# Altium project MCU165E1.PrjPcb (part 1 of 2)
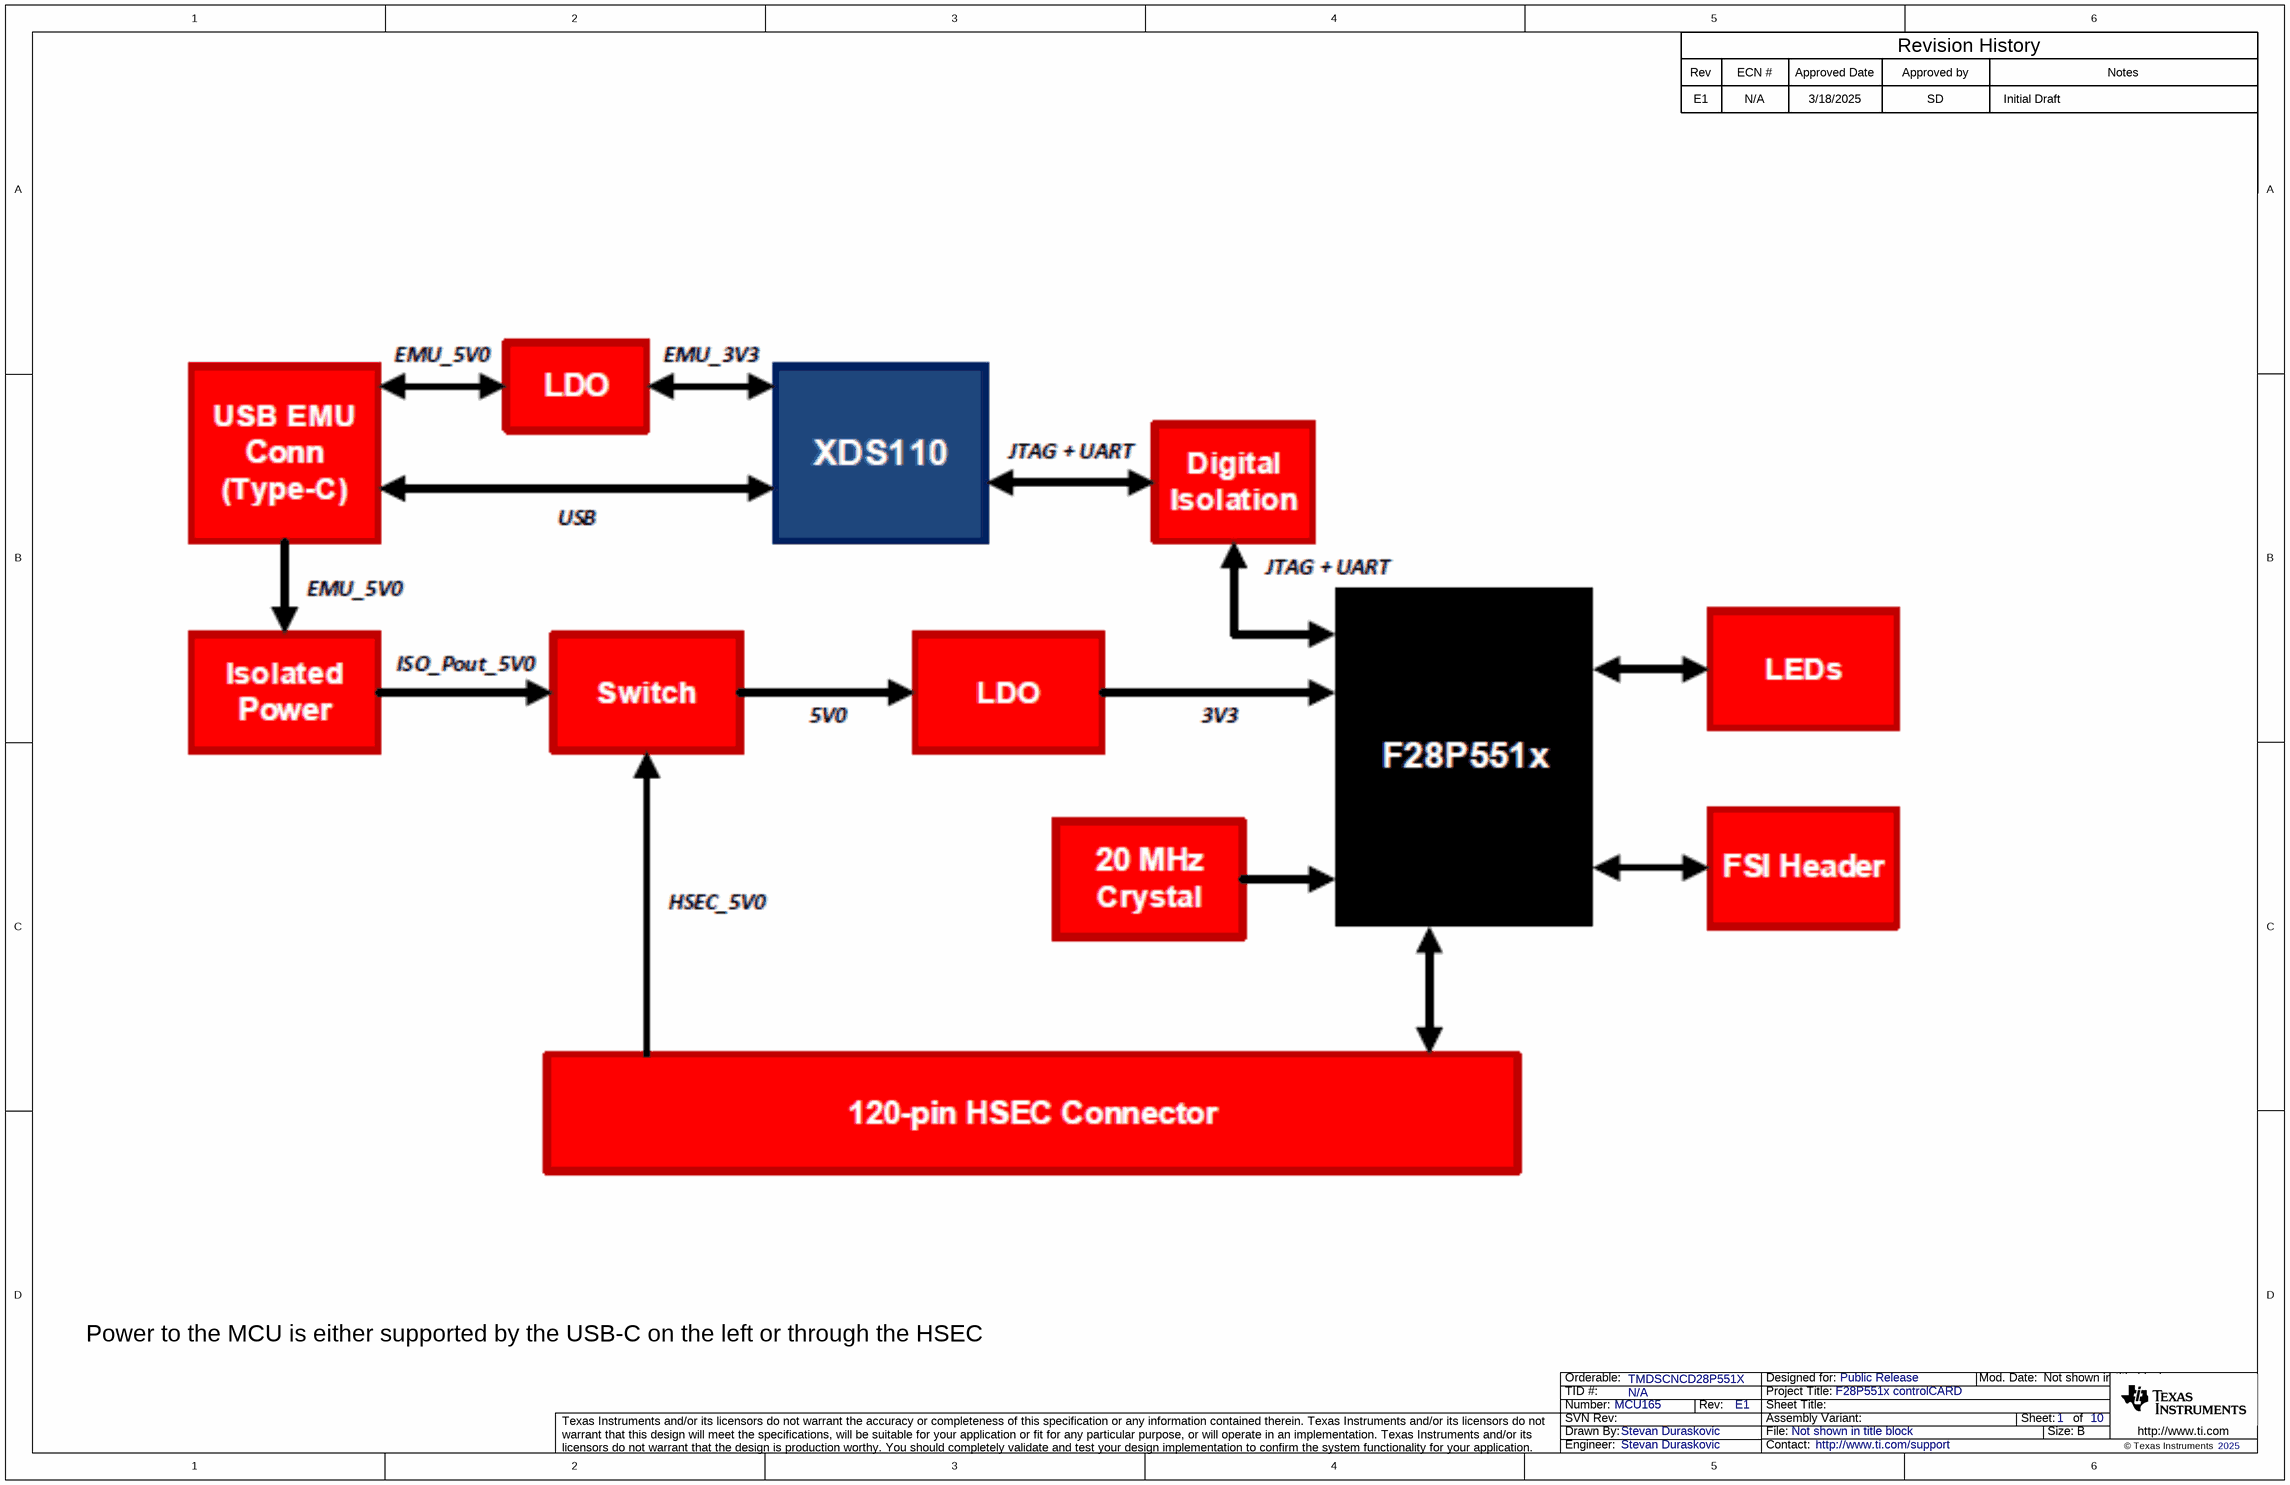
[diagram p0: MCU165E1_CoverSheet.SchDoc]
CopyrightYear: 2025; DrawnBy: Stevan Duraskovic; EVM_Orderable: TMDSCNCD28P551X; PCB_Layout: Stevan Duraskovic; PCB_Rev: E1; PRJ_Customer: Public Release; PRJ_Engineer: Stevan Duraskovic; PRJ_Number: MCU165; PRJ_Title: F28P551x controlCARD; SCH_Rev: E1; TechSupport: http://www.ti.com/support; TID: N/A
9 sheets, 227 parts. Net scope: global (net labels, ports and power ports of the same name join across sheets).
Board file: MCU165E1_PCB.PcbDoc
Sheets:
  MCU165E1_CoverSheet.SchDoc
  MCU165E1_GPIO.SchDoc
  MCU165E1_Support.SchDoc
  MCU165E1_Power.SchDoc
  MCU165E1_ADC.SchDoc
  MCU165E1_XDS110_USB_Power.SchDoc
  MCU165E1_XDS110_MCU.SchDoc
  MCU165E1_Emulator_Interface.SchDoc
  MCU165E1_Hardware.SchDoc

## Sheet MCU165E1_CoverSheet.SchDoc
size 431 x 279 mm; Date: Not shown in title block; ApprovedBy: Not shown in title block; CheckedBy: Not shown in title block; Author: Not shown in title block; CompanyName: Not shown in title block; Engineer: Not shown in title block; Organization: Not shown in title block; Address1: Not shown in title block; Address2: Not shown in title block; Address3: Not shown in title block; Address4: Not shown in title block; DocumentNumber: 1; Revision: Use project parameter SCH_Rev; SheetNumber: 1; SheetTotal: 10; PageSetup: Record=PageOptions¦CenterHorizontal=True¦CenterVertical=True¦PrintScale=1.00¦XCorrection=1.00¦YCorrection=1.00¦PrintKind=0¦BorderSize=5000000¦LeftOffset=0¦BottomOffset=0¦Orientation=2¦PaperLength=1000¦PaperWidth=1000¦Scale=100¦PaperSource=15¦PrintQuality=600¦MediaType=1¦DitherType=10¦PaperKind=Letter¦PrintScaleMode=1

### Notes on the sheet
- Rev
- E1
- ECN #
- N/A
- Approved Date
- 3/18/2025
- Approved by
- SD
- Revision History
- Initial Draft
- Notes
- Power to the MCU is either supported by the USB-C on the left or through the HSEC 180 pin.

## Sheet MCU165E1_GPIO.SchDoc
size 431 x 279 mm; Date: Not shown in title block; ApprovedBy: Not shown in title block; CheckedBy: Not shown in title block; Author: Not shown in title block; CompanyName: Not shown in title block; Engineer: Not shown in title block; Organization: Not shown in title block; Address1: Not shown in title block; Address2: Not shown in title block; Address3: Not shown in title block; Address4: Not shown in title block; DocumentNumber: 2; Revision: Use project parameter SCH_Rev; SheetNumber: 2; SheetTotal: 10; PageSetup: Record=PageOptions¦CenterHorizontal=True¦CenterVertical=True¦PrintScale=1.00¦XCorrection=1.00¦YCorrection=1.00¦PrintKind=0¦BorderSize=5000000¦LeftOffset=0¦BottomOffset=0¦Orientation=2¦PaperLength=1000¦PaperWidth=1000¦Scale=100¦PaperSource=15¦PrintQuality=600¦MediaType=1¦DitherType=10¦PaperKind=Letter¦PrintScaleMode=1
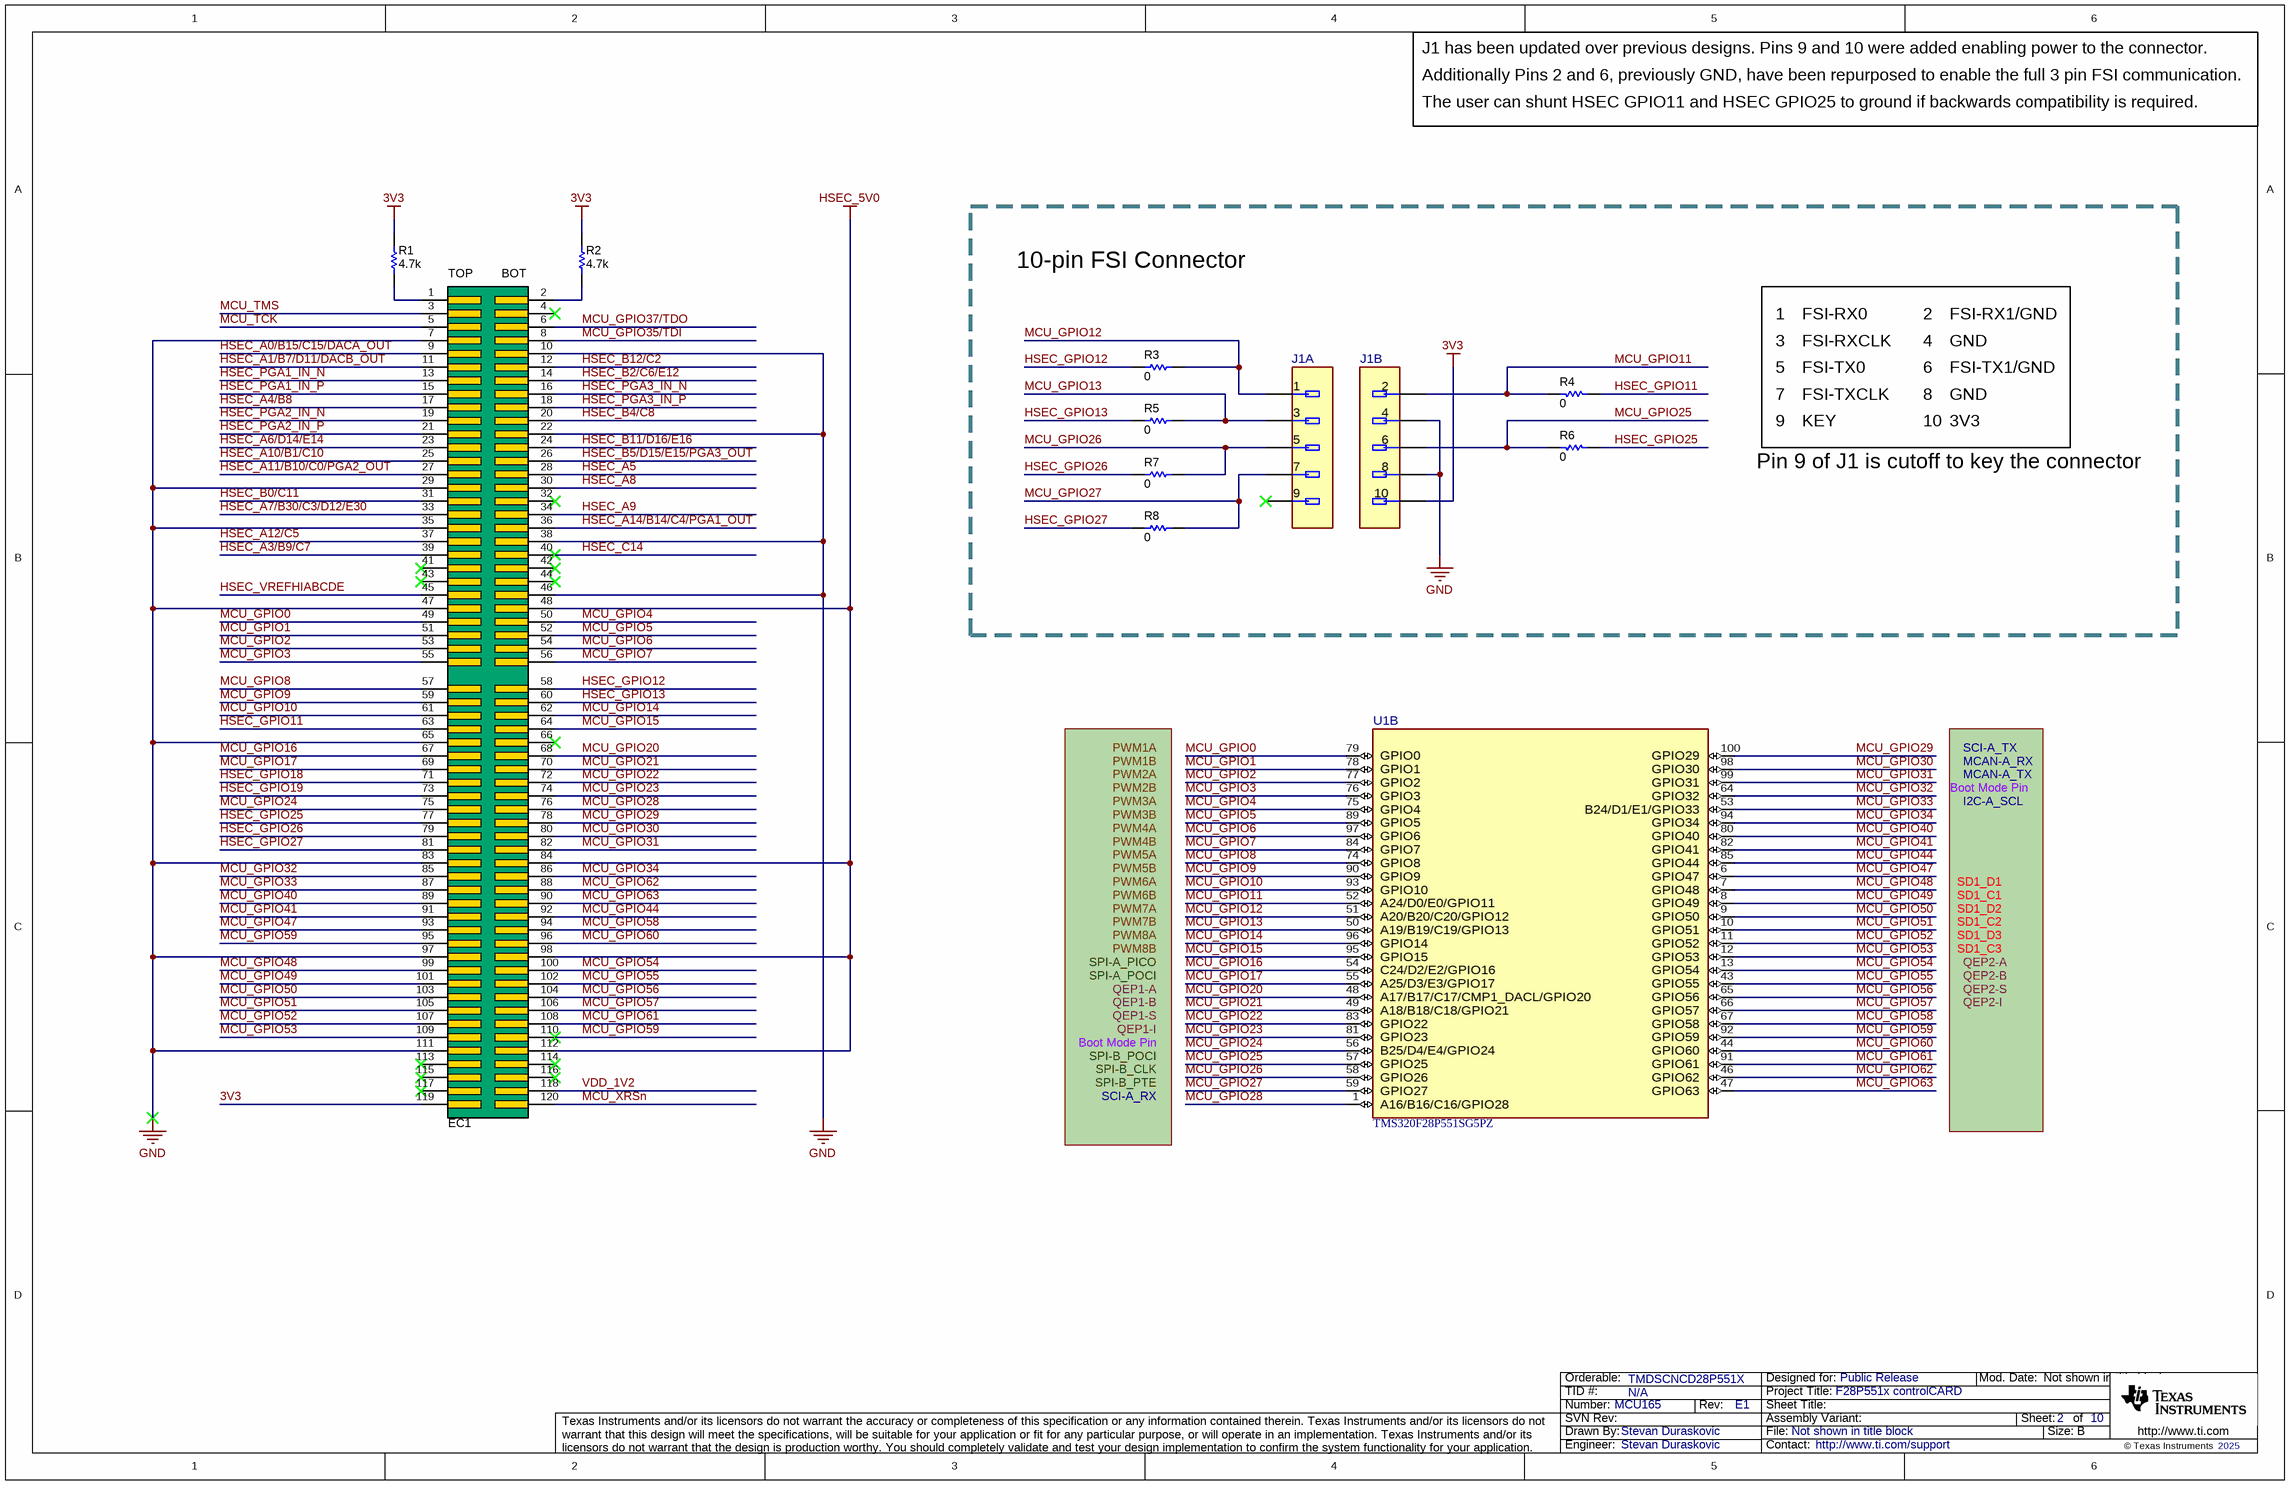
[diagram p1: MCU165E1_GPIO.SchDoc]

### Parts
EC1  controlCARD-120HSEC_Edge  [controlCARD-120HSEC_Edge]  (value not drawn)  (no BOM)
J1  TMM-105-01-T-D  [FP-TMM-105-01-T-D_HDR10-MFG]  (value not drawn)  (parts A,B of 2)
R1  ValueDisplayed: 4.7k  [0402]  (hidden comment: CRCW04024K70JNED)
R2  ValueDisplayed: 4.7k  [0402]  (hidden comment: CRCW04024K70JNED)
R3  ValueDisplayed: 0  [0603]  (hidden comment: CRCW06030000Z0EA)
R4  ValueDisplayed: 0  [0603]  (hidden comment: CRCW06030000Z0EA)
R5  ValueDisplayed: 0  [0603]  (hidden comment: CRCW06030000Z0EA)
R6  ValueDisplayed: 0  [0603]  (hidden comment: CRCW06030000Z0EA)
R7  ValueDisplayed: 0  [0603]  (hidden comment: CRCW06030000Z0EA)
R8  ValueDisplayed: 0  [0603]  (hidden comment: CRCW06030000Z0EA)
U1  TMS320F28P551SG5PZ  [PZ0100A-MFG]  (part B of 4)

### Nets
3V3: EC1.119 J1.10 R1.1 R2.2
GND: EC1.7 EC1.10 EC1.22 EC1.29 EC1.35 EC1.38 EC1.46 EC1.47 EC1.65 EC1.83 EC1.97 EC1.111 J1.4 J1.8
HSEC_5V0: EC1.48 EC1.84 EC1.98 EC1.112
VDD_1V2: EC1.118
HSEC_A0/B15/C15/DACA_OUT: EC1.9
HSEC_A1/B7/D11/DACB_OUT: EC1.11
HSEC_A3/B9/C7: EC1.39
HSEC_A4/B8: EC1.17
HSEC_A5: EC1.28
HSEC_A6/D14/E14: EC1.23
HSEC_A7/B30/C3/D12/E30: EC1.33
HSEC_A8: EC1.30
HSEC_A9: EC1.34
HSEC_A10/B1/C10: EC1.25
HSEC_A11/B10/C0/PGA2_OUT: EC1.27
HSEC_A12/C5: EC1.37
HSEC_A14/B14/C4/PGA1_OUT: EC1.36
HSEC_B0/C11: EC1.31
HSEC_B2/C6/E12: EC1.14
HSEC_B4/C8: EC1.20
HSEC_B5/D15/E15/PGA3_OUT: EC1.26
HSEC_B11/D16/E16: EC1.24
HSEC_B12/C2: EC1.12
HSEC_C14: EC1.40
HSEC_GPIO11: EC1.63 R4.1
HSEC_GPIO12: EC1.58 R3.1
HSEC_GPIO13: EC1.60 R5.1
HSEC_GPIO18: EC1.71
HSEC_GPIO19: EC1.73
HSEC_GPIO25: EC1.77 R6.1
HSEC_GPIO26: EC1.79 R7.1
HSEC_GPIO27: EC1.81 R8.1
HSEC_PGA1_IN_N: EC1.13
HSEC_PGA1_IN_P: EC1.15
HSEC_PGA2_IN_N: EC1.19
HSEC_PGA2_IN_P: EC1.21
HSEC_PGA3_IN_N: EC1.16
HSEC_PGA3_IN_P: EC1.18
HSEC_VREFHIABCDE: EC1.45
MCU_GPIO0: EC1.49 U1.79(GPIO0)
MCU_GPIO1: EC1.51 U1.78(GPIO1)
MCU_GPIO2: EC1.53 U1.77(GPIO2)
MCU_GPIO3: EC1.55 U1.76(GPIO3)
MCU_GPIO4: EC1.50 U1.75(GPIO4)
MCU_GPIO5: EC1.52 U1.89(GPIO5)
MCU_GPIO6: EC1.54 U1.97(GPIO6)
MCU_GPIO7: EC1.56 U1.84(GPIO7)
MCU_GPIO8: EC1.57 U1.74(GPIO8)
MCU_GPIO9: EC1.59 U1.90(GPIO9)
MCU_GPIO10: EC1.61 U1.93(GPIO10)
MCU_GPIO11: J1.2 R4.2 U1.52(A24/D0/E0/GPIO11)
MCU_GPIO12: J1.1 R3.2 U1.51(A20/B20/C20/GPIO12)
MCU_GPIO13: J1.3 R5.2 U1.50(A19/B19/C19/GPIO13)
MCU_GPIO14: EC1.62 U1.96(GPIO14)
MCU_GPIO15: EC1.64 U1.95(GPIO15)
MCU_GPIO16: EC1.67 U1.54(C24/D2/E2/GPIO16)
MCU_GPIO17: EC1.69 U1.55(A25/D3/E3/GPIO17)
MCU_GPIO20: EC1.68 U1.48(A17/B17/C17/CMP1_DACL/GPIO20)
MCU_GPIO21: EC1.70 U1.49(A18/B18/C18/GPIO21)
MCU_GPIO22: EC1.72 U1.83(GPIO22)
MCU_GPIO23: EC1.74 U1.81(GPIO23)
MCU_GPIO24: EC1.75 U1.56(B25/D4/E4/GPIO24)
MCU_GPIO25: J1.6 R6.2 U1.57(GPIO25)
MCU_GPIO26: J1.5 R7.2 U1.58(GPIO26)
MCU_GPIO27: J1.7 R8.2 U1.59(GPIO27)
MCU_GPIO28: EC1.76 U1.1(A16/B16/C16/GPIO28)
MCU_GPIO29: EC1.78 U1.100(GPIO29)
MCU_GPIO30: EC1.80 U1.98(GPIO30)
MCU_GPIO31: EC1.82 U1.99(GPIO31)
MCU_GPIO32: EC1.85 U1.64(GPIO32)
MCU_GPIO33: EC1.87 U1.53(B24/D1/E1/GPIO33)
MCU_GPIO34: EC1.86 U1.94(GPIO34)
MCU_GPIO35/TDI: EC1.8
MCU_GPIO37/TDO: EC1.6
MCU_GPIO40: EC1.89 U1.80(GPIO40)
MCU_GPIO41: EC1.91 U1.82(GPIO41)
MCU_GPIO44: EC1.92 U1.85(GPIO44)
MCU_GPIO47: EC1.93 U1.6(GPIO47)
MCU_GPIO48: EC1.99 U1.7(GPIO48)
MCU_GPIO49: EC1.101 U1.8(GPIO49)
MCU_GPIO50: EC1.103 U1.9(GPIO50)
MCU_GPIO51: EC1.105 U1.10(GPIO51)
MCU_GPIO52: EC1.107 U1.11(GPIO52)
MCU_GPIO53: EC1.109 U1.12(GPIO53)
MCU_GPIO54: EC1.100 U1.13(GPIO54)
MCU_GPIO55: EC1.102 U1.43(GPIO55)
MCU_GPIO56: EC1.104 U1.65(GPIO56)
MCU_GPIO57: EC1.106 U1.66(GPIO57)
MCU_GPIO58: EC1.94 U1.67(GPIO58)
MCU_GPIO59: EC1.95 EC1.110 U1.92(GPIO59)
MCU_GPIO60: EC1.96 U1.44(GPIO60)
MCU_GPIO61: EC1.108 U1.91(GPIO61)
MCU_GPIO62: EC1.88 U1.46(GPIO62)
MCU_GPIO63: EC1.90 U1.47(GPIO63)
MCU_TCK: EC1.5
MCU_TMS: EC1.3
MCU_XRSn: EC1.120
NetEC1_1: EC1.1 R1.2
NetEC1_2: EC1.2 R2.1

Not connected (* = marked no-connect by the designer): EC1 4* 32* 41* 42* 43* 44* 66* 113* 114* 115* 116* 117*; J1 9*

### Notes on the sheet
- J1 has been updated over previous designs. Pins 9 and 10 were added enabling power to the connector.
- Additionally Pins 2 and 6, previously GND, have been repurposed to enable the full 3 pin FSI communication.
- The user can shunt HSEC GPIO11 and HSEC GPIO25 to ground if backwards compatibility is required.
- 10-pin FSI Connector
- 1
- 3
- 5
- FSI-RX0
- FSI-RXCLK
- FSI-TX0
- 2
- 4
- 6
- FSI-RX1/GND
- GND
- FSI-TX1/GND
- 7
- 9
- FSI-TXCLK
- KEY
- 8
- 10
- 3V3
- Pin 9 of J1 is cutoff to key the connector
- PWM1A
- PWM1B
- SCI-A_TX
- MCAN-A_RX
- PWM2A
- PWM2B
- PWM3A
- PWM3B
- PWM4A
- MCAN-A_TX
- I2C-A_SCL
- Boot Mode Pin
- PWM4B
- PWM5A
- PWM5B
- PWM6A
- PWM6B
- SD1_D1
- SD1_C1
- PWM8A
- PWM8B
- PWM7B
- PWM7A
- SPI-A_PICO
- QEP2-A
- SD1_D2
- SD1_C2
- SD1_D3
- SD1_C3
- QEP1-S
- QEP1-A
- QEP1-B
- SPI-A_POCI
- QEP1-I
- QEP2-B
- QEP2-S
- QEP2-I
- SPI-B_POCI
- SPI-B_CLK
- SPI-B_PTE
- SCI-A_RX

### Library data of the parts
EC1 = CMP-0003813-2: C2000 controlCARD-120HSEC Edge Connector for Samtec HSEC8-160-01-L-DV-A-BL; Manufacturer: Any; Note: The pin numbering does not match Samtec datasheet
J1 = CMP-0086568-1: Board-To-Board Connector, TMM Series, 10 Contacts, Header, 2 mm, Through Hole, 2 Rows; Manufacturer: Samtec; ContactFinish: Tin,Nickel; Voltage_V: 281V; Symbol Name: SYM-TMM-105-01-T-D; Row_Count: 2; Current_A: 3.2A
R1 R2 = CMP-0026938-5: RES, 4.7 k, 5%, 0.063 W, AEC-Q200 Grade 0, 0402; Manufacturer: Vishay-Dale; Value: 4.7k; Value_Code: 4k70; Power_W: 63mW; Value2: 0.063W; VDC_V: 50V; TempCo: 200 ppm/C; EIA_Code: E24; AEC Category: Q200; AEC Qualified: Y; AEC Grade: 0; SizeArea_mm2: 0.5; SizeX_mm: 1; SizeZ_mm: 0.6
R3-R8 = CMP-0025697-4: RES, 0, 5%, 0.1 W, AEC-Q200 Grade 0, 0603; Manufacturer: Vishay-Dale; Value: 0; Value_Code: 0000; Power_W: 100mW; Value2: 0.1W; VDC_V: 75V; TempCo: 200 ppm/C; EIA_Code: E24; AEC Category: Q200; AEC Qualified: Y; SizeArea_mm2: 1.28; SizeX_mm: 1.6; SizeY_mm: 0.8; SizeZ_mm: 1
U1 = CMP-0124912-2: Real-Time Microcontroller, LQFP100; Manufacturer: Texas Instruments; SizeZ_mm: 1.6mm; AEC Qualified: No; AEC Grade: NA; Core Architecture: C28x; Data Bus Width: 32bits; Frequency_Fixed: 160MHz; Interface: I2C,SPI,UART,CAN,LIN,SCI; Max Supply Voltage: 3.63V; Memory Size: 512KBytes; Memory Type: FLASH; Min Supply Voltage: 1.14V; Number Of A/D Converters: 5; Number Of Adc Channels: 35; Number Of Cores: 1; Number Of I/Os: 43; Number Of I2C Channels: 2; Number Of Pwm Channels: 24; Number Of Timers/Counters: 3; Ram Size: 101KBytes; Standoff Height: 0.05mm; TaMax_C: +125°C; TaMin_C: -40°C; TJmax_C: +150°C; AEC Category: Q200; CompType: IC

## Sheet MCU165E1_Support.SchDoc
size 431 x 279 mm; Date: Not shown in title block; ApprovedBy: Not shown in title block; CheckedBy: Not shown in title block; Author: Not shown in title block; CompanyName: Not shown in title block; Engineer: Not shown in title block; Organization: Not shown in title block; Address1: Not shown in title block; Address2: Not shown in title block; Address3: Not shown in title block; Address4: Not shown in title block; DocumentNumber: 3; Revision: Use project parameter SCH_Rev; SheetNumber: 3; SheetTotal: 10; PageSetup: Record=PageOptions¦CenterHorizontal=True¦CenterVertical=True¦PrintScale=1.00¦XCorrection=1.00¦YCorrection=1.00¦PrintKind=0¦BorderSize=5000000¦LeftOffset=0¦BottomOffset=0¦Orientation=2¦PaperLength=1000¦PaperWidth=1000¦Scale=100¦PaperSource=15¦PrintQuality=600¦MediaType=1¦DitherType=10¦PaperKind=Letter¦PrintScaleMode=1
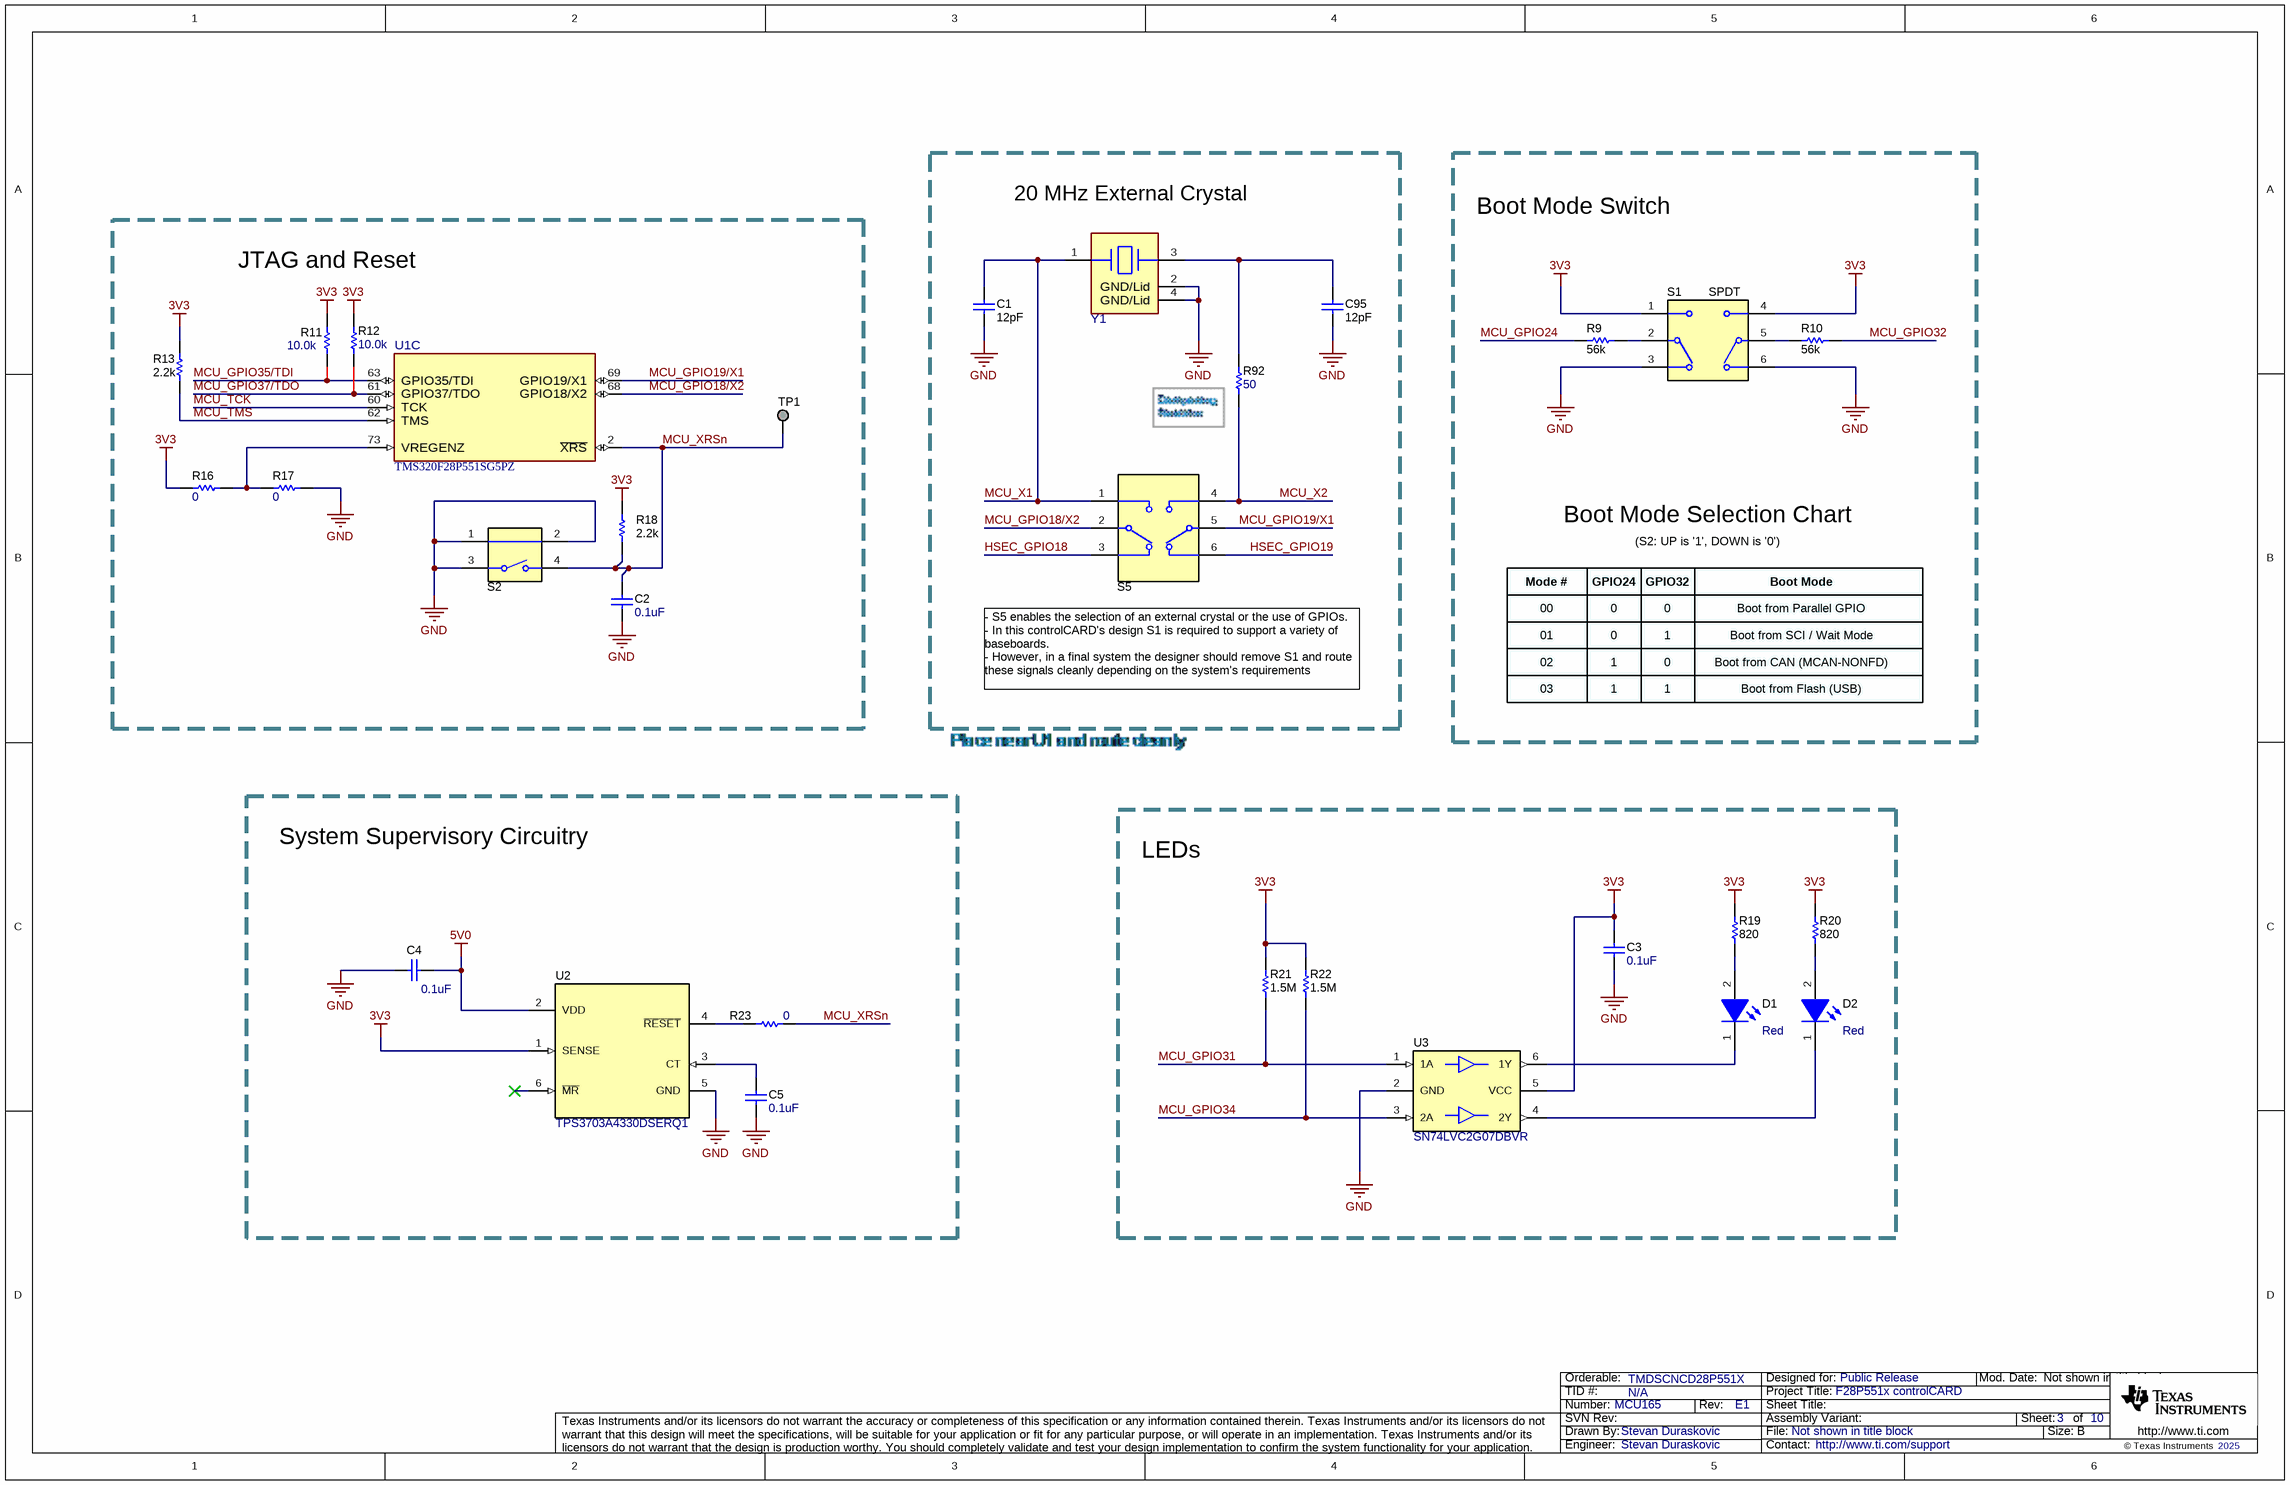
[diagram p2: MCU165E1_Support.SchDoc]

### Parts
C1  ValueDisplayed: 12pF  [0402]  (hidden comment: CL05C120JB5NNNC)
C2  ValueDisplayed: 0.1uF  [0402]  (hidden comment: 885012205037)
C3  ValueDisplayed: 0.1uF  [0402]  (hidden comment: 885012205037)
C4  ValueDisplayed: 0.1uF  [0402]  (hidden comment: 885012205037)
C5  ValueDisplayed: 0.1uF  [0402]  (hidden comment: 885012205037)
C95  ValueDisplayed: 12pF  [0402]  (hidden comment: CL05C120JB5NNNC)
D1  value Red  [WL-SMCW_RED_0805]  (hidden comment: 150080SS75000)
D2  value Red  [WL-SMCW_RED_0805]  (hidden comment: 150080SS75000)
R9  ValueDisplayed: 56k  [0402]  (hidden comment: CRCW040256K0JNED)
R10  ValueDisplayed: 56k  [0402]  (hidden comment: CRCW040256K0JNED)
R11  ValueDisplayed: 10.0k  [0402]  (hidden comment: AC0402FR-0710KL)
R12  ValueDisplayed: 10.0k  [0402]  (hidden comment: AC0402FR-0710KL)
R13  ValueDisplayed: 2.2k  [0402]  (hidden comment: CRCW04022K20JNED)
R16  ValueDisplayed: 0  [0402]  (hidden comment: ERJ-2GE0R00X)
R17  ValueDisplayed: 0  [0402]  (hidden comment: ERJ-2GE0R00X)
R18  ValueDisplayed: 2.2k  [0402]  (hidden comment: CRCW04022K20JNED)
R19  ValueDisplayed: 820  [0402]  (hidden comment: CRCW0402820RJNED)
R20  ValueDisplayed: 820  [0402]  (hidden comment: CRCW0402820RJNED)
R21  ValueDisplayed: 1.5M  [0402]  (hidden comment: CRCW04021M50JNED)
R22  ValueDisplayed: 1.5M  [0402]  (hidden comment: CRCW04021M50JNED)
R23  ValueDisplayed: 0  [0603]  (hidden comment: ERJ-3GEY0R00V)
R92  ValueDisplayed: 50  [0603]  (hidden comment: FC0603E50R0BTBST1)
S1  Circuit: SPDT  [SW_CAS-D20TA]  (hidden comment: CAS-D20TA)
S2  1188E-1K2-V-TR  [SW_1188E]  (value not drawn)
S5  CAS-220TA  [SW_CAS-220TA]  (value not drawn)
TP1  TESTPOINT  [TP_50MIL-25MILHOLE]  (value not drawn)  (no BOM)
U1  TMS320F28P551SG5PZ  [PZ0100A-MFG]  (part C of 4)
U2  TPS3703A4330DSERQ1  [DSE0006A]
U3  SN74LVC2G07DBVR  [DBV0006A_N]
Y1  830108207209  [FP-830108207209_SMT_CRYSTAL_3MM2_2MM5-MFG]  (value not drawn)

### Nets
3V3: C3.1 R11.2 R12.2 R13.2 R16.1 R18.2 R19.2 R20.2 R21.2 R22.2 S1.1 S1.4 U2.1(SENSE) U3.5(VCC)
5V0: C4.1 U2.2(VDD)
GND: C1.2 C2.2 C3.2 C4.2 C5.2 C95.2 R17.2 S1.3 S1.6 S2.1 S2.2 S2.3 U2.5(GND) U3.2(GND) Y1.2(GND/Lid) Y1.4(GND/Lid)
HSEC_GPIO18: S5.3
HSEC_GPIO19: S5.6
MCU_GPIO18/X2: S5.2 U1.68(GPIO18/X2)
MCU_GPIO19/X1: S5.5 U1.69(GPIO19/X1)
MCU_GPIO24: R9.2
MCU_GPIO31: R21.1 U3.1(1A)
MCU_GPIO32: R10.1
MCU_GPIO34: R22.1 U3.3(2A)
MCU_GPIO35/TDI: R11.1 U1.63(GPIO35/TDI)
MCU_GPIO37/TDO: R12.1 U1.61(GPIO37/TDO)
MCU_TCK: U1.60(TCK)
MCU_TMS: R13.1 U1.62(TMS)
MCU_X1: C1.1 S5.1 Y1.1(1_Crystal)
MCU_X2: R92.1 S5.4
MCU_XRSn: C2.1 R18.1 R23.1 S2.4 TP1.1 U1.2(~{XRS})
NetC5_1: C5.1 U2.3(CT)
NetC95_1: C95.1 R92.2 Y1.3(2_Crystal)
NetD1_1: D1.1(K) U3.6(1Y)
NetD1_2: D1.2(A) R19.1
NetD2_1: D2.1(K) U3.4(2Y)
NetD2_2: D2.2(A) R20.1
NetR9_1: R9.1 S1.2(C)
NetR10_2: R10.2 S1.5(C)
NetR16_2: R16.2 R17.1 U1.73(VREGENZ)
NetR23_2: R23.2 U2.4(~{RESET})

Not connected (* = marked no-connect by the designer): U2 6(~{MR})*

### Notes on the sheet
- 20 MHz External Crystal
- Boot Mode Switch
- JTAG and Reset
- Boot Mode Selection Chart
- (S2: UP is '1', DOWN is '0')
- Mode #
- 00
- 01
- GPIO24
- 0
- GPIO32
- 1
- Boot Mode
- Boot from Parallel GPIO
- Boot from SCI / Wait Mode
- - S5 enables the selection of an external crystal or the use of GPIOs.
  - In this controlCARD's design S1 is required to support a variety of               baseboards.
  - However, in a final system the designer should remove S1 and route these signals cleanly depending on the system's requirements
- 02
- 03
- Boot from CAN (MCAN-NONFD)
- Boot from Flash (USB)
- System Supervisory Circuitry
- LEDs

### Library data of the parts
C1 C95 = CMP-0006345-2: CAP, CERM, 12 pF, 50 V, +/- 5%, C0G/NP0, 0402; Manufacturer: Samsung Electro-Mechanics; Polarized: N; Value: 12pF; U/M: EA; Value1: Unknown; VDC_V: 50V; TaMin_C: -55°C; TaMax_C: 125°C; SizeArea_mm2: 0.5; SizeAreaWB_mm2: 3; SizeX_mm: 1; SizeZ_mm: 0.6; AEC Category: Q200
C2-C5 = CMP-0006228-2: CAP, CERM, 0.1 uF, 16 V, +/- 10%, X7R, 0402; Manufacturer: Wurth Elektronik; TaMin_C: -55°C; Polarized: N; SizeAreaWB_mm2: 3; Value1: Unknown; U/M: EA; Value: 0.1uF; TaMax_C: 125°C; SizeZ_mm: 0.6; SizeX_mm: 1; SizeY_mm: 0.5; Value2: 16V; Cap_F: 100nF; AEC Category: Q200
D1 D2 = CMP-0002951-3: LED, Red, SMD; Manufacturer: Wurth Elektronik; Type: AlInGaP; Vf_V: 1.9V; Io_A: 30mA; Vr_V: 5V; Ir_A: 25µA; Tjmax_C: 85°C; Power_TotalModule: 72mW; Value1: 0.072W; Angle: 140
R9 R10 = CMP-0026949-3: RES, 56 k, 5%, 0.063 W, AEC-Q200 Grade 0, 0402; Manufacturer: Vishay-Dale; Value: 56k; Value_Code: 56k0; Power_W: 63mW; Value2: 0.063W; VDC_V: 50V; TempCo: 200 ppm/C; EIA_Code: E24; AEC Category: Q200; AEC Qualified: Y; AEC Grade: 0; SizeArea_mm2: 0.5; SizeX_mm: 1; SizeZ_mm: 0.6
R11 R12 = CMP-0077731-1: RES, 10.0 k, 1%, 0.063 W, AEC-Q200 Grade 0, 0402; Manufacturer: Yageo America; Power_W: 63mW; TempCo: 100 ppm/C; Value_Code: 10k0; U/M: EA; Value: 10.0k; EIA_Code: E96; Res_ohm: 10k; SizeX_mm: 1.0; SizeY_mm: 0.5; SizeZ_mm: 0.6; Value2: 0.063W; AEC Qualified: Y; VDC_V: 50V; AEC Grade: 0; AEC Category: Q200
R13 R18 = CMP-0026890-5: RES, 2.2 k, 5%, 0.063 W, AEC-Q200 Grade 0, 0402; Manufacturer: Vishay-Dale; Value: 2.2k; Value_Code: 2k20; Power_W: 63mW; Value2: 0.063W; VDC_V: 50V; TempCo: 200 ppm/C; EIA_Code: E24; AEC Category: Q200; AEC Qualified: Y; AEC Grade: 0; SizeArea_mm2: 0.5; SizeX_mm: 1; SizeZ_mm: 0.6
R16 R17 = CMP-0026992-3: RES, 0, 5%, 0.1 W, AEC-Q200 Grade 0, 0402; Manufacturer: Panasonic; Power_W: 100mW; TempCo: 600 ppm/C; Value_Code: 0000; Value: 0; EIA_Code: E24; SizeX_mm: 1; SizeY_mm: 0.5; SizeZ_mm: 0.6; Value2: 0.1W; AEC Qualified: Y; VDC_V: 50V; AEC Category: Q200; SizeAreaWB_mm2: 3
R19 R20 = CMP-0026979-3: RES, 820, 5%, 0.063 W, AEC-Q200 Grade 0, 0402; Manufacturer: Vishay-Dale; Power_W: 63mW; TempCo: 200 ppm/C; Value_Code: 820R; Value: 820; EIA_Code: E24; SizeX_mm: 1; SizeY_mm: 0.5; SizeZ_mm: 0.6; Value2: 0.063W; AEC Qualified: Y; VDC_V: 50V; AEC Category: Q200; AEC Grade: 0
R21 R22 = CMP-0026863-2: RES, 1.5 M, 5%, 0.063 W, AEC-Q200 Grade 0, 0402; Manufacturer: Vishay-Dale; Power_W: 63mW; TempCo: 200 ppm/C; Value_Code: 1M50; Value: 1.5Meg; EIA_Code: E24; SizeX_mm: 1; SizeY_mm: 0.5; SizeZ_mm: 0.6; Value2: 0.063W; AEC Qualified: Y; VDC_V: 50V; AEC Category: Q200; AEC Grade: 0
R23 = CMP-0025874-4: RES, 0, 5%, 0.1 W, AEC-Q200 Grade 0, 0603; Manufacturer: Panasonic; Power_W: 100mW; TempCo: 600 ppm/C; Value_Code: 0000; Value: 0; EIA_Code: E24; SizeX_mm: 1.6; SizeY_mm: 0.8; SizeZ_mm: 1; Value2: 0.1W; SizeArea_mm2: 1.28; AEC Qualified: Y; VDC_V: 50V; AEC Category: Q200; SizeAreaWB_mm2: 4.68
R92 = CMP-0023387-3: RES, 50, 0.1%, 0.125 W, 0603; Manufacturer: Vishay Thin Film; Power_W: 125mW; TempCo: 25 ppm/C; Value_Code: 50R0; U/M: EA; Value: 50; SizeX_mm: 1.6; SizeY_mm: 0.8; SizeZ_mm: 1; Value2: 0.125W; SizeArea_mm2: 1.28; AEC Qualified: N; VDC_V: 50V; AEC Category: Q200
S1 = CMP-0002233-1: Switch, Dual SPDT,  2 Pos, 0.1A, 6VDC, SMD; Manufacturer: Copal Electronics; VDC_V: 6V; SwitchFunction: On-On; PositionCount: 2; CurrentRating_mA: 100A
S2 = CMP-0002328-1: Switch, SPST, 0.05 A, 12 VDC, SMD; Manufacturer: Diptronics; SizeAreaWB_mm2: 53.9; SizeArea_mm2: 27.3; SizeX_mm: 7.8; SizeY_mm: 3.5; VDC_V: 12V; PositionCount: 1; CurrentRating_mA: 50A
S5 = CMP-0002123-2: SLIDE SWITCH DPDT  .1A, SMT; Manufacturer: Copal Electronics; CurrentRating_mA: 100A; SwitchFunction: On-On; VDC_V: 6V; PositionCount: 2
TP1 = CMP-0078143-3: TEST POINT.  No entry in BOM.
U1 = CMP-0124912-2: as U1 on sheet MCU165E1_GPIO
U2 = CMP-0750051-1: Overvoltage and Undervoltage Reset IC With Time Delay and Manual Reset, DSE0006A (WSON-6); Alternate Manufacturer: Texas Instruments; AEC Category: Q200; SizeY_mm: 1.5; AEC Qualified: Y; SizeAreaWB_mm2: 6.25; SizeZ_mm: 0.8; SizeArea_mm2: 2.25
U3 = CMP-0051789-2: Dual Buffer/Driver with Open-Drain Output, DBV0006A, LARGE T&R; Manufacturer: Texas Instruments; 3-State Output: No; Bits(#): 2; F @ Nom Voltage(Max)(Mhz): 150; ICC @ Nom Voltage(Max)(mA): 0.01; Input Type: CMOS/TTL; Logic: True; Output Drive (IOL/IOH)(Max)(mA): 32/-32; Output Type: CMOS; Rating: Catalog; Sub-Family: Inverting Buffer/Driver; Technology Family: LVC; tpd @ Nom Voltage(Max)(ns): 8.6,4.4,3.7,2.9; VCC(Max)(V): 5.5; VCC(Min)(V): 1.65; Voltage(Nom)(V): 1.8,2.5,3.3,5; AEC Category: Q200; AEC Qualified: N; CompType: IC; Green_Lifecycle: Active; Green_REACh: Passed; SizeArea_mm2: 8.12; SizeAreaWB_mm2: 14.82; SizeX_mm: 2.8; SizeY_mm: 2.9; SizeZ_mm: 1.45
Y1 = CMP-0093781-1: 20 MHz ±10ppm Crystal 8pF 50 Ohms 4-SMD, No Lead; Manufacturer: Wurth Electronics; SizeZ_mm: 0.8mm; Frequency Stability: 20ppm; Esr: 50; Frequency_Fixed: 20MHz

## Sheet MCU165E1_Power.SchDoc
size 431 x 279 mm; Date: Not shown in title block; ApprovedBy: Not shown in title block; CheckedBy: Not shown in title block; Author: Not shown in title block; CompanyName: Not shown in title block; Engineer: Not shown in title block; Organization: Not shown in title block; Address1: Not shown in title block; Address2: Not shown in title block; Address3: Not shown in title block; Address4: Not shown in title block; DocumentNumber: 4; Revision: Use project parameter SCH_Rev; SheetNumber: 4; SheetTotal: 10; PageSetup: Record=PageOptions¦CenterHorizontal=True¦CenterVertical=True¦PrintScale=1.00¦XCorrection=1.00¦YCorrection=1.00¦PrintKind=0¦BorderSize=5000000¦LeftOffset=0¦BottomOffset=0¦Orientation=2¦PaperLength=1000¦PaperWidth=1000¦Scale=100¦PaperSource=15¦PrintQuality=600¦MediaType=1¦DitherType=10¦PaperKind=Letter¦PrintScaleMode=1
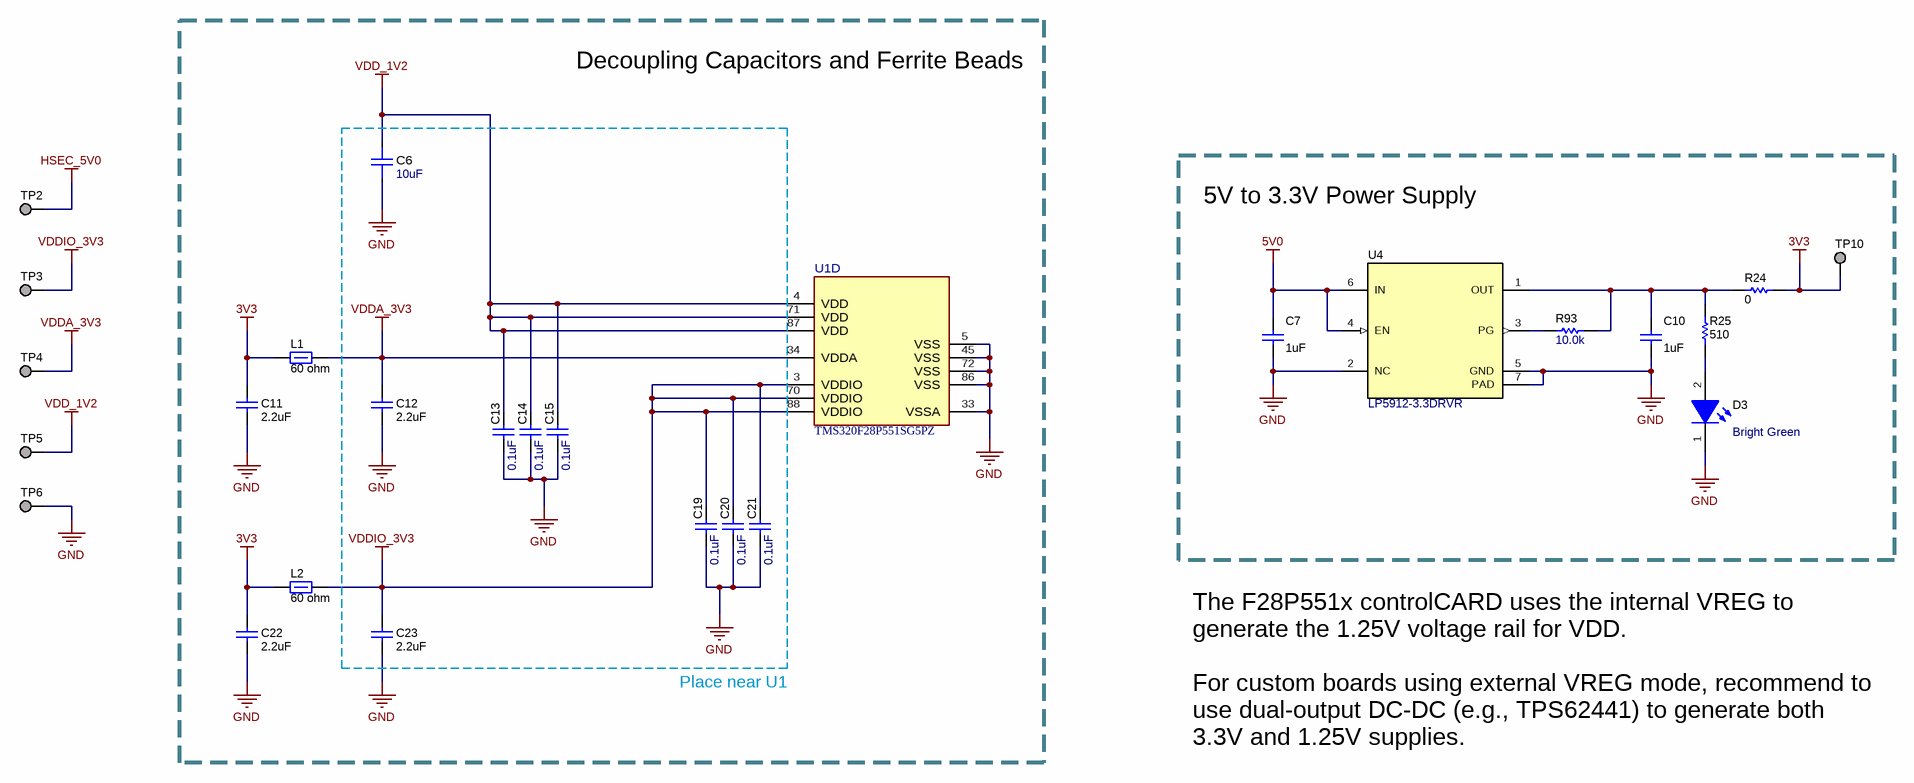
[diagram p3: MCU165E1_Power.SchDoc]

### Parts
C6  ValueDisplayed: 10uF  [FP-CC0603KRX5R7BB106_0603-MFG]  (hidden comment: CC0603KRX5R7BB106)
C7  ValueDisplayed: 1uF  [0402]  (hidden comment: 885012105012)
C10  ValueDisplayed: 1uF  [0402]  (hidden comment: 885012105012)
C11  ValueDisplayed: 2.2uF  [0603]  (hidden comment: 885012106018)
C12  ValueDisplayed: 2.2uF  [0603]  (hidden comment: 885012106018)
C13  ValueDisplayed: 0.1uF  [0402]  (hidden comment: 885012205037)
C14  ValueDisplayed: 0.1uF  [0402]  (hidden comment: 885012205037)
C15  ValueDisplayed: 0.1uF  [0402]  (hidden comment: 885012205037)
C19  ValueDisplayed: 0.1uF  [0402]  (hidden comment: 885012205037)
C20  ValueDisplayed: 0.1uF  [0402]  (hidden comment: 885012205037)
C21  ValueDisplayed: 0.1uF  [0402]  (hidden comment: 885012205037)
C22  ValueDisplayed: 2.2uF  [0603]  (hidden comment: 885012106018)
C23  ValueDisplayed: 2.2uF  [0603]  (hidden comment: 885012106018)
D3  value Bright Green  [WL-SMCW_Green_0805]  (hidden comment: 150080VS75000)
L1  60 ohm  [0805_HV]
L2  60 ohm  [0805_HV]
R24  ValueDisplayed: 0  [0805_HV]  (hidden comment: CRCW08050000Z0EA)
R25  ValueDisplayed: 510  [0402]  (hidden comment: CRCW0402510RJNED)
R93  ValueDisplayed: 10.0k  [0402]  (hidden comment: AC0402FR-0710KL)
TP2  TESTPOINT  [TP_50MIL-25MILHOLE]  (value not drawn)  (no BOM)
TP3  TESTPOINT  [TP_50MIL-25MILHOLE]  (value not drawn)  (no BOM)
TP4  TESTPOINT  [TP_50MIL-25MILHOLE]  (value not drawn)  (no BOM)
TP5  TESTPOINT  [TP_50MIL-25MILHOLE]  (value not drawn)  (no BOM)
TP6  TESTPOINT  [TP_50MIL-25MILHOLE]  (value not drawn)  (no BOM)
TP10  TESTPOINT  [TP_50MIL-25MILHOLE]  (value not drawn)  (no BOM)
U1  TMS320F28P551SG5PZ  [PZ0100A-MFG]  (part D of 4)
U4  LP5912-3.3DRVR  [DRV0006A]

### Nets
3V3: C11.1 C22.1 L1.1 L2.1 R24.2 TP10.1
5V0: C7.1 U4.4(EN) U4.6(IN)
GND: C6.1 C7.2 C10.2 C11.2 C12.2 C13.2 C14.2 C15.2 C19.2 C20.2 C21.2 C22.2 C23.2 D3.1(K) TP6.1 U1.5(VSS) U1.33(VSSA) U1.45(VSS) U1.72(VSS) U1.86(VSS) U4.2(NC) U4.5(GND) U4.7(PAD)
HSEC_5V0: TP2.1
VDD_1V2: C6.2 C13.1 C14.1 C15.1 TP5.1 U1.4(VDD) U1.71(VDD) U1.87(VDD)
VDDA_3V3: C12.1 L1.2 TP4.1 U1.34(VDDA)
VDDIO_3V3: C19.1 C20.1 C21.1 C23.1 L2.2 TP3.1 U1.3(VDDIO) U1.70(VDDIO) U1.88(VDDIO)
NetC10_1: C10.1 R24.1 R25.2 R93.1 U4.1(OUT)
NetD3_2: D3.2(A) R25.1
NetR93_2: R93.2 U4.3(PG)

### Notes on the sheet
- Decoupling Capacitors and Ferrite Beads
- 5V to 3.3V Power Supply
- Place near U1
- The F28P551x controlCARD uses the internal VREG to generate the 1.25V voltage rail for VDD.
  For custom boards using external VREG mode, recommend to use dual-output DC-DC (e.g., TPS62441) to generate both 3.3V and 1.25V supplies.

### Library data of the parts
C6 = CMP-0001560-1: Multilayer Ceramic Capacitors 10uF 16V X5R 10% SMD 0603 85°C Paper T/R - Tape an; Manufacturer: Yageo; AEC Qualified: No; Cap_F: 10µF; SizeZ_mm: 1mm; TempCo: 15%; Value: 10µF
C7 C10 = CMP-0064924-2: CAP, CERM, 1 uF, 10 V,+/- 20%, X5R, 0402; Manufacturer: Wurth Elektronik; TaMin_C: -55°C; Polarized: N; SizeAreaWB_mm2: 3; Value1: Unknown; U/M: EA; Value: 1uF; TaMax_C: 85°C; SizeZ_mm: 0.6; SizeX_mm: 1; SizeY_mm: 0.5; Value2: 10V; Cap_F: 1µF; AEC Category: Q200
C11 C12 C22 C23 = CMP-0006825-5: CAP, CERM, 2.2 uF, 16 V, +/- 20%, X5R, 0603; Manufacturer: Wurth Elektronik; TaMin_C: -55°C; Polarized: N; SizeAreaWB_mm2: 4.68; Value1: Unknown; U/M: EA; Value: 2.2uF; TaMax_C: 85°C; SizeZ_mm: 1; SizeX_mm: 1.6; SizeY_mm: 0.8; Value2: 16V; SizeArea_mm2: 1.28; Cap_F: 2.2µF; AEC Category: Q200
C13-C15 C19-C21 = CMP-0006228-2: as C2 on sheet MCU165E1_Support
D3 = CMP-0002960-2: LED, Bright Green, SMD; Manufacturer: Wurth Elektronik; Type: AlInGaP; Vf_V: 2V; Io_A: 20mA; Vr_V: 5V; Tjmax_C: 85°C; Power_TotalModule: 72mW; Value1: 0.072W; Angle: 140; U/M: EA
L1 L2 = CMP-0003093-1: Ferrite Bead, 60 ohm @ 100 MHz, 3 A, 0805; Manufacturer: Wurth Elektronik; PartNumber: 742792063; Ztyp@1GHz_Ohm: 95.384; ZTyp@100MHz_Ohm: 60; SizeAreaWB_mm2: 6.75; DCR_ohm: 0.025; Value1: 0.025 ohm; Imax_A: 3A; SizeZ_mm: 1.45; SizeX_mm: 2; SizeY_mm: 1.25; SizeArea_mm2: 2.5
R24 = CMP-0020442-3: RES, 0, 5%, 0.125 W, AEC-Q200 Grade 0, 0805; Manufacturer: Vishay-Dale; Value: 0; Value_Code: 0000; Power_W: 125mW; Value2: 0.125W; VDC_V: 150V; TempCo: 200 ppm/C; EIA_Code: E24; AEC Category: Q200; AEC Qualified: Y; SizeArea_mm2: 2.5; SizeX_mm: 2; SizeY_mm: 1.25; SizeZ_mm: 1.45
R25 = CMP-0026944-3: RES, 510, 5%, 0.063 W, AEC-Q200 Grade 0, 0402; Manufacturer: Vishay-Dale; Power_W: 63mW; TempCo: 200 ppm/C; Value_Code: 510R; Value: 510; EIA_Code: E24; SizeX_mm: 1; SizeY_mm: 0.5; SizeZ_mm: 0.6; Value2: 0.063W; AEC Qualified: Y; VDC_V: 50V; AEC Category: Q200; AEC Grade: 0
R93 = CMP-0077731-1: as R11 on sheet MCU165E1_Support
TP2-TP6 TP10 = CMP-0078143-3: TEST POINT.  No entry in BOM.
U1 = CMP-0124912-2: as U1 on sheet MCU165E1_GPIO
U4 = CMP-0076262-4: 500-mA Low-Noise, Low-IQ LDO, DRV0006A (WSON-6); Manufacturer: Texas Instruments; Alternate PartNumber: LP5912-3.3DRVT; SizeX_mm: 2; CompType: IC; SizeZ_mm: 0.8; SizeArea_mm2: 4; SizeAreaWB_mm2: 9; U/M: EA; Green_Lifecycle: Active; Green_REACh: Passed

## Sheet MCU165E1_ADC.SchDoc
size 431 x 279 mm; Date: Not shown in title block; ApprovedBy: Not shown in title block; CheckedBy: Not shown in title block; Author: Not shown in title block; CompanyName: Not shown in title block; Engineer: Not shown in title block; Organization: Not shown in title block; Address1: Not shown in title block; Address2: Not shown in title block; Address3: Not shown in title block; Address4: Not shown in title block; DocumentNumber: 5; Revision: Use project parameter SCH_Rev; SheetNumber: 5; SheetTotal: 10; PageSetup: Record=PageOptions¦CenterHorizontal=True¦CenterVertical=True¦PrintScale=1.00¦XCorrection=1.00¦YCorrection=1.00¦PrintKind=0¦BorderSize=5000000¦LeftOffset=0¦BottomOffset=0¦Orientation=2¦PaperLength=1000¦PaperWidth=1000¦Scale=100¦PaperSource=15¦PrintQuality=600¦MediaType=1¦DitherType=10¦PaperKind=Letter¦PrintScaleMode=1
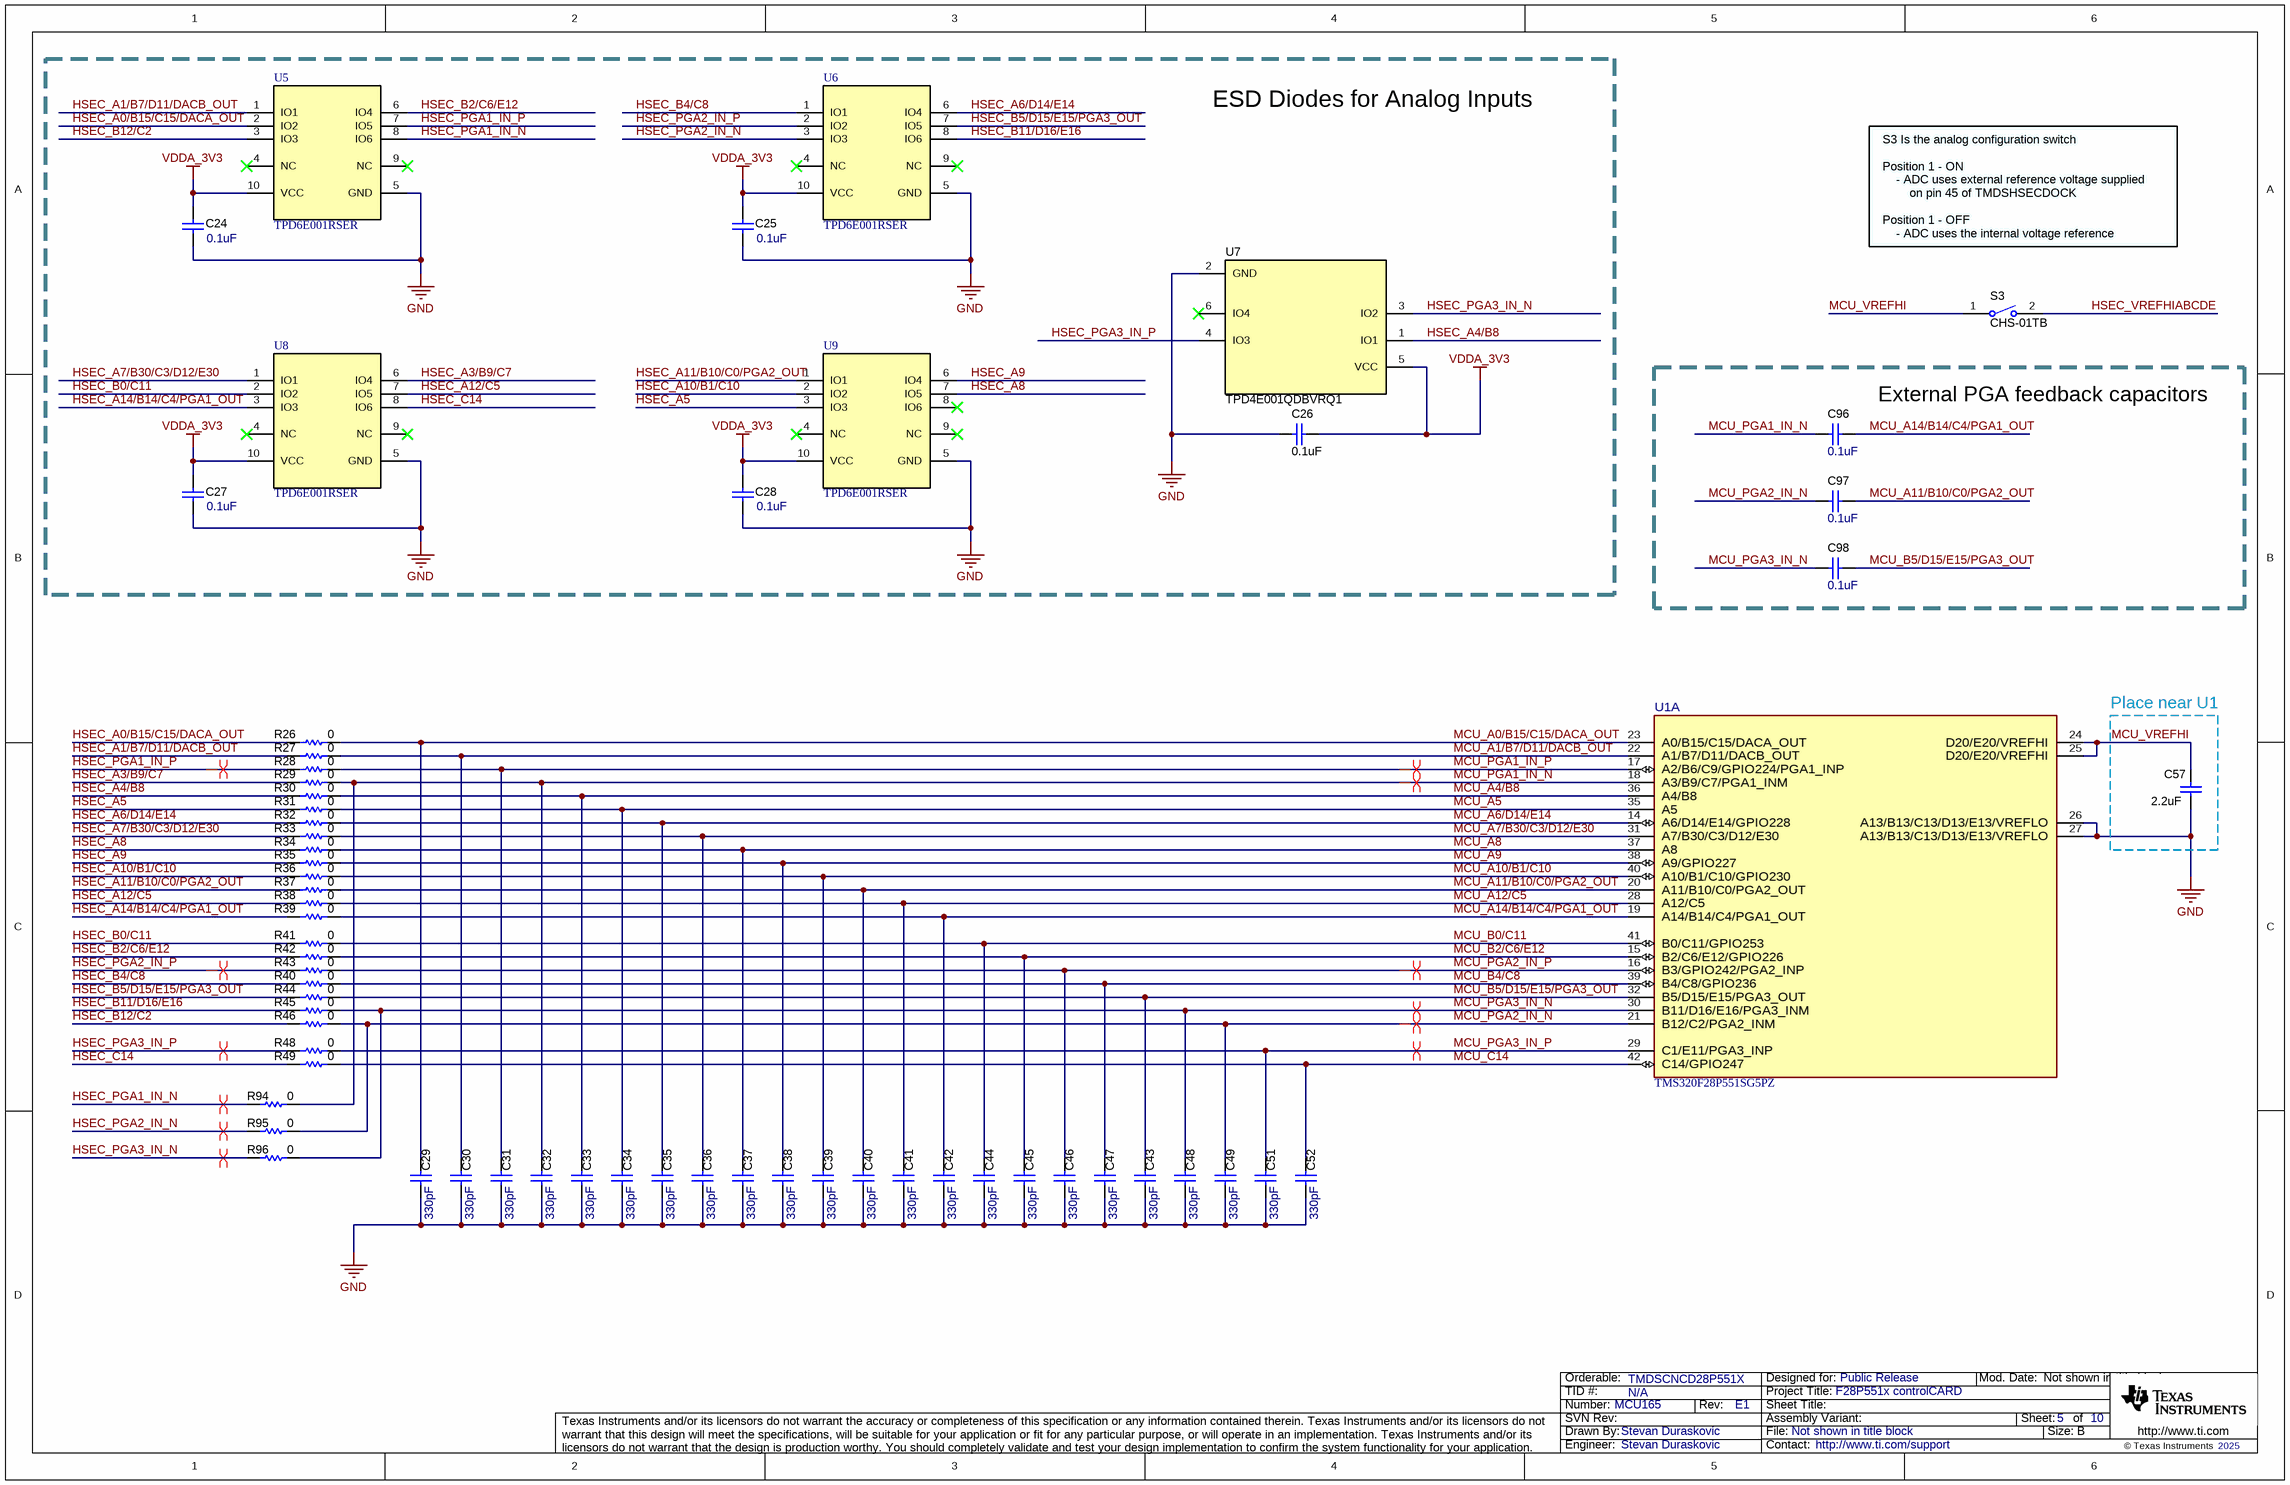
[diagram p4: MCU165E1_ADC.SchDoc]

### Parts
C24  Cap_F: 0.1uF  [0603]  (hidden comment: 885012206046)
C25  Cap_F: 0.1uF  [0603]  (hidden comment: 885012206046)
C26  ValueDisplayed: 0.1uF  [0603]  (hidden comment: C0603C104K8RACTU)
C27  Cap_F: 0.1uF  [0603]  (hidden comment: 885012206046)
C28  Cap_F: 0.1uF  [0603]  (hidden comment: 885012206046)
C29  ValueDisplayed: 330pF  [0603]  (hidden comment: C0603C331J5GACTU)
C30  ValueDisplayed: 330pF  [0603]  (hidden comment: C0603C331J5GACTU)
C31  ValueDisplayed: 330pF  [0603]  (hidden comment: C0603C331J5GACTU)
C32  ValueDisplayed: 330pF  [0603]  (hidden comment: C0603C331J5GACTU)
C33  ValueDisplayed: 330pF  [0603]  (hidden comment: C0603C331J5GACTU)
C34  ValueDisplayed: 330pF  [0603]  (hidden comment: C0603C331J5GACTU)
C35  ValueDisplayed: 330pF  [0603]  (hidden comment: C0603C331J5GACTU)
C36  ValueDisplayed: 330pF  [0603]  (hidden comment: C0603C331J5GACTU)
C37  ValueDisplayed: 330pF  [0603]  (hidden comment: C0603C331J5GACTU)
C38  ValueDisplayed: 330pF  [0603]  (hidden comment: C0603C331J5GACTU)
C39  ValueDisplayed: 330pF  [0603]  (hidden comment: C0603C331J5GACTU)
C40  ValueDisplayed: 330pF  [0603]  (hidden comment: C0603C331J5GACTU)
C41  ValueDisplayed: 330pF  [0603]  (hidden comment: C0603C331J5GACTU)
C42  ValueDisplayed: 330pF  [0603]  (hidden comment: C0603C331J5GACTU)
C43  ValueDisplayed: 330pF  [0603]  (hidden comment: C0603C331J5GACTU)
C44  ValueDisplayed: 330pF  [0603]  (hidden comment: C0603C331J5GACTU)
C45  ValueDisplayed: 330pF  [0603]  (hidden comment: C0603C331J5GACTU)
C46  ValueDisplayed: 330pF  [0603]  (hidden comment: C0603C331J5GACTU)
C47  ValueDisplayed: 330pF  [0603]  (hidden comment: C0603C331J5GACTU)
C48  ValueDisplayed: 330pF  [0603]  (hidden comment: C0603C331J5GACTU)
C49  ValueDisplayed: 330pF  [0603]  (hidden comment: C0603C331J5GACTU)
C51  ValueDisplayed: 330pF  [0603]  (hidden comment: C0603C331J5GACTU)
C52  ValueDisplayed: 330pF  [0603]  (hidden comment: C0603C331J5GACTU)
C57  ValueDisplayed: 2.2uF  [0603]  (hidden comment: 885012106018)
C96  Cap_F: 0.1uF  [0603]  (hidden comment: 885012206046)
C97  Cap_F: 0.1uF  [0603]  (hidden comment: 885012206046)
C98  Cap_F: 0.1uF  [0603]  (hidden comment: 885012206046)
R26  ValueDisplayed: 0  [0603]  (hidden comment: CRCW06030000Z0EA)
R27  ValueDisplayed: 0  [0603]  (hidden comment: CRCW06030000Z0EA)
R28  ValueDisplayed: 0  [0603]  (hidden comment: CRCW06030000Z0EA)
R29  ValueDisplayed: 0  [0603]  (hidden comment: CRCW06030000Z0EA)
R30  ValueDisplayed: 0  [0603]  (hidden comment: CRCW06030000Z0EA)
R31  ValueDisplayed: 0  [0603]  (hidden comment: CRCW06030000Z0EA)
R32  ValueDisplayed: 0  [0603]  (hidden comment: CRCW06030000Z0EA)
R33  ValueDisplayed: 0  [0603]  (hidden comment: CRCW06030000Z0EA)
R34  ValueDisplayed: 0  [0603]  (hidden comment: CRCW06030000Z0EA)
R35  ValueDisplayed: 0  [0603]  (hidden comment: CRCW06030000Z0EA)
R36  ValueDisplayed: 0  [0603]  (hidden comment: CRCW06030000Z0EA)
R37  ValueDisplayed: 0  [0603]  (hidden comment: CRCW06030000Z0EA)
R38  ValueDisplayed: 0  [0603]  (hidden comment: CRCW06030000Z0EA)
R39  ValueDisplayed: 0  [0603]  (hidden comment: CRCW06030000Z0EA)
R40  ValueDisplayed: 0  [0603]  (hidden comment: CRCW06030000Z0EA)
R41  ValueDisplayed: 0  [0603]  (hidden comment: CRCW06030000Z0EA)
R42  ValueDisplayed: 0  [0603]  (hidden comment: CRCW06030000Z0EA)
R43  ValueDisplayed: 0  [0603]  (hidden comment: CRCW06030000Z0EA)
R44  ValueDisplayed: 0  [0603]  (hidden comment: CRCW06030000Z0EA)
R45  ValueDisplayed: 0  [0603]  (hidden comment: CRCW06030000Z0EA)
R46  ValueDisplayed: 0  [0603]  (hidden comment: CRCW06030000Z0EA)
R48  ValueDisplayed: 0  [0603]  (hidden comment: CRCW06030000Z0EA)
R49  ValueDisplayed: 0  [0603]  (hidden comment: CRCW06030000Z0EA)
R94  ValueDisplayed: 0  [0603]  (hidden comment: CRCW06030000Z0EA)
R95  ValueDisplayed: 0  [0603]  (hidden comment: CRCW06030000Z0EA)
R96  ValueDisplayed: 0  [0603]  (hidden comment: CRCW06030000Z0EA)
S3  CHS-01TB  [SW_CHS-01TB]
U1  TMS320F28P551SG5PZ  [PZ0100A-MFG]  (part A of 4)
U5  TPD6E001RSER  [RSE0010A]
U6  TPD6E001RSER  [RSE0010A]
U7  TPD4E001QDBVRQ1  [DBV0006A_N]
U8  TPD6E001RSER  [RSE0010A]
U9  TPD6E001RSER  [RSE0010A]

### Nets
GND: C24.2 C25.2 C26.1 C27.2 C28.2 C29.2 C30.2 C31.2 C32.2 C33.2 C34.2 C35.2 C36.2 C37.2 C38.2 C39.2 C40.2 C41.2 C42.2 C43.2 C44.2 C45.2 C46.2 C47.2 C48.2 C49.2 C51.2 C52.2 C57.2 U1.26(A13/B13/C13/D13/E13/VREFLO) U1.27(A13/B13/C13/D13/E13/VREFLO) U5.5(GND) U6.5(GND) U7.2(GND) U8.5(GND) U9.5(GND)
VDDA_3V3: C24.1 C25.1 C26.2 C27.1 C28.1 U5.10(VCC) U6.10(VCC) U7.5(VCC) U8.10(VCC) U9.10(VCC)
HSEC_A0/B15/C15/DACA_OUT: R26.2 U5.2(IO2)
HSEC_A1/B7/D11/DACB_OUT: R27.2 U5.1(IO1)
HSEC_A3/B9/C7: R29.2 U8.6(IO4)
HSEC_A4/B8: R30.2 U7.1(IO1)
HSEC_A5: R31.2 U9.3(IO3)
HSEC_A6/D14/E14: R32.2 U6.6(IO4)
HSEC_A7/B30/C3/D12/E30: R33.2 U8.1(IO1)
HSEC_A8: R34.2 U9.7(IO5)
HSEC_A9: R35.2 U9.6(IO4)
HSEC_A10/B1/C10: R36.2 U9.2(IO2)
HSEC_A11/B10/C0/PGA2_OUT: R37.2 U9.1(IO1)
HSEC_A12/C5: R38.2 U8.7(IO5)
HSEC_A14/B14/C4/PGA1_OUT: R39.2 U8.3(IO3)
HSEC_B0/C11: R41.2 U8.2(IO2)
HSEC_B2/C6/E12: R42.2 U5.6(IO4)
HSEC_B4/C8: R40.2 U6.1(IO1)
HSEC_B5/D15/E15/PGA3_OUT: R44.2 U6.7(IO5)
HSEC_B11/D16/E16: R45.2 U6.8(IO6)
HSEC_B12/C2: R46.2 U5.3(IO3)
HSEC_C14: R49.2 U8.8(IO6)
HSEC_PGA1_IN_N: R94.2 U5.8(IO6)
HSEC_PGA1_IN_P: R28.2 U5.7(IO5)
HSEC_PGA2_IN_N: R95.2 U6.3(IO3)
HSEC_PGA2_IN_P: R43.2 U6.2(IO2)
HSEC_PGA3_IN_N: R96.2 U7.3(IO2)
HSEC_PGA3_IN_P: R48.2 U7.4(IO3)
HSEC_VREFHIABCDE: S3.2
MCU_A0/B15/C15/DACA_OUT: C29.1 R26.1 U1.23(A0/B15/C15/DACA_OUT)
MCU_A1/B7/D11/DACB_OUT: C30.1 R27.1 U1.22(A1/B7/D11/DACB_OUT)
MCU_A4/B8: C33.1 R30.1 U1.36(A4/B8)
MCU_A5: C34.1 R31.1 U1.35(A5)
MCU_A6/D14/E14: C35.1 R32.1 U1.14(A6/D14/E14/GPIO228)
MCU_A7/B30/C3/D12/E30: C36.1 R33.1 U1.31(A7/B30/C3/D12/E30)
MCU_A8: C37.1 R34.1 U1.37(A8)
MCU_A9: C38.1 R35.1 U1.38(A9/GPIO227)
MCU_A10/B1/C10: C39.1 R36.1 U1.40(A10/B1/C10/GPIO230)
MCU_A11/B10/C0/PGA2_OUT: C40.1 C97.2 R37.1 U1.20(A11/B10/C0/PGA2_OUT)
MCU_A12/C5: C41.1 R38.1 U1.28(A12/C5)
MCU_A14/B14/C4/PGA1_OUT: C42.1 C96.2 R39.1 U1.19(A14/B14/C4/PGA1_OUT)
MCU_B0/C11: C44.1 R41.1 U1.41(B0/C11/GPIO253)
MCU_B2/C6/E12: C45.1 R42.1 U1.15(B2/C6/E12/GPIO226)
MCU_B4/C8: C47.1 R40.1 U1.39(B4/C8/GPIO236)
MCU_B5/D15/E15/PGA3_OUT: C43.1 C98.2 R44.1 U1.32(B5/D15/E15/PGA3_OUT)
MCU_C14: C52.1 R49.1 U1.42(C14/GPIO247)
MCU_PGA1_IN_N: C32.1 C96.1 R29.1 R94.1 U1.18(A3/B9/C7/PGA1_INM)
MCU_PGA1_IN_P: C31.1 R28.1 U1.17(A2/B6/C9/GPIO224/PGA1_INP)
MCU_PGA2_IN_N: C49.1 C97.1 R46.1 R95.1 U1.21(B12/C2/PGA2_INM)
MCU_PGA2_IN_P: C46.1 R43.1 U1.16(B3/GPIO242/PGA2_INP)
MCU_PGA3_IN_N: C48.1 C98.1 R45.1 R96.1 U1.30(B11/D16/E16/PGA3_INM)
MCU_PGA3_IN_P: C51.1 R48.1 U1.29(C1/E11/PGA3_INP)
MCU_VREFHI: C57.1 S3.1 U1.24(D20/E20/VREFHI) U1.25(D20/E20/VREFHI)

Not connected (* = marked no-connect by the designer): U5 4(NC)* 9(NC)*; U6 4(NC)* 9(NC)*; U7 6(IO4)*; U8 4(NC)* 9(NC)*; U9 4(NC)* 8(IO6)* 9(NC)*

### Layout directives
differential pair: HSEC_PGA1_IN_N, HSEC_PGA1_IN_P, HSEC_PGA2_IN_N, HSEC_PGA2_IN_P, HSEC_PGA3_IN_N, HSEC_PGA3_IN_P, MCU_PGA1_IN_N, MCU_PGA1_IN_P, MCU_PGA2_IN_N, MCU_PGA2_IN_P, MCU_PGA3_IN_N, MCU_PGA3_IN_P

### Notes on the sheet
- ESD Diodes for Analog Inputs
- S3 Is the analog configuration switch
- Position 1 - ON
- Position 1 - OFF
- - ADC uses external reference voltage supplied
- - ADC uses the internal voltage reference
- on pin 45 of TMDSHSECDOCK
- (near C96) External PGA feedback capacitors
- Place near U1

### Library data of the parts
C24 C25 C27 C28 C96-C98 = CMP-0006829-4: CAP, CERM, 0.1 uF, 16 V, +/- 10%, X7R, 0603; Manufacturer: Wurth Elektronik; TaMin_C: -55°C; Polarized: N; SizeAreaWB_mm2: 4.68; Value1: Unknown; U/M: EA; Value: 0.1uF; TaMax_C: 125°C; SizeZ_mm: 1; SizeX_mm: 1.6; SizeY_mm: 0.8; Value2: 16V; SizeArea_mm2: 1.28; AEC Category: Q200
C26 = CMP-0006862-5: CAP, CERM, 0.1 uF, 10 V, +/- 10%, X7R, 0603; Manufacturer: Kemet; TaMin_C: -55°C; Polarized: N; SizeAreaWB_mm2: 4.68; Value1: Unknown; U/M: EA; Value: 0.1uF; TaMax_C: 125°C; SizeZ_mm: 1; SizeX_mm: 1.6; SizeY_mm: 0.8; Value2: 10V; SizeArea_mm2: 1.28; Cap_F: 100nF; AEC Category: Q200
C29-C49 C51 C52 = CMP-0006920-4: CAP, CERM, 330 pF, 50 V, +/- 5%, C0G/NP0, 0603; Manufacturer: Kemet; TaMin_C: -55°C; Polarized: N; SizeAreaWB_mm2: 4.68; Value1: Unknown; U/M: EA; Value: 330pF; TaMax_C: 125°C; SizeZ_mm: 1; SizeX_mm: 1.6; SizeY_mm: 0.8; Value2: 50V; SizeArea_mm2: 1.28; AEC Category: Q200
C57 = CMP-0006825-5: as C11 on sheet MCU165E1_Power
R26-R46 R48 R49 R94-R96 = CMP-0025697-4: as R3 on sheet MCU165E1_GPIO
S3 = CMP-0002163-2: Switch, Slide, SPST, Top Slide, SMT; Manufacturer: Copal Electronics; CurrentRating_mA: 100A; SwitchFunction: Off-On; VDC_V: 6V; PositionCount: 1
U1 = CMP-0124912-2: as U1 on sheet MCU165E1_GPIO
U5 U6 U8 U9 = CMP-0043123-1: Low-Capacitance + / - 15 kV ESD Protection Array for High-Speed Data Interfaces, 6 Channels, -40 to +85 degC, 10-pin UQFN (RSE), Green (RoHS & no Sb/Br); Manufacturer: Texas Instruments; Serial ATA / eSATA: TRUE; IO Leakage Current(nA): 1; IO Capacitance(Typ)(pF): 1.5; IEC 61000-4-2 Contact(+/- kV): 8; Breakdown Voltage(Min)(V): 11; IEC 61000-4-2 Air-Gap(+/- kV): 15; SubFamily: ESD Solution
U7 = CMP-0066599-1: Automotive Low-Capacitance 4-Channel +/-15-kV ESD Protection Array for High-Speed Data Interfaces, DBV0006A (SOT-23-6); Alternate Manufacturer: Texas Instruments; SizeAreaWB_mm2: 14.82; U/M: EA; SizeZ_mm: 1.45; SizeX_mm: 2.8; SizeY_mm: 2.9; SizeArea_mm2: 8.12; CompType: IC

## Sheet MCU165E1_XDS110_USB_Power.SchDoc
size 431 x 279 mm; Date: Not shown in title block; ApprovedBy: Not shown in title block; CheckedBy: Not shown in title block; Author: Not shown in title block; CompanyName: Not shown in title block; Engineer: Not shown in title block; Organization: Not shown in title block; Address1: Not shown in title block; Address2: Not shown in title block; Address3: Not shown in title block; Address4: Not shown in title block; DocumentNumber: 7; Revision: Use project parameter SCH_Rev; SheetNumber: 7; SheetTotal: 10; PageSetup: Record=PageOptions¦CenterHorizontal=True¦CenterVertical=True¦PrintScale=1.00¦XCorrection=1.00¦YCorrection=1.00¦PrintKind=0¦BorderSize=5000000¦LeftOffset=0¦BottomOffset=0¦Orientation=2¦PaperLength=1000¦PaperWidth=1000¦Scale=100¦PaperSource=15¦PrintQuality=600¦MediaType=1¦DitherType=10¦PaperKind=Letter¦PrintScaleMode=1
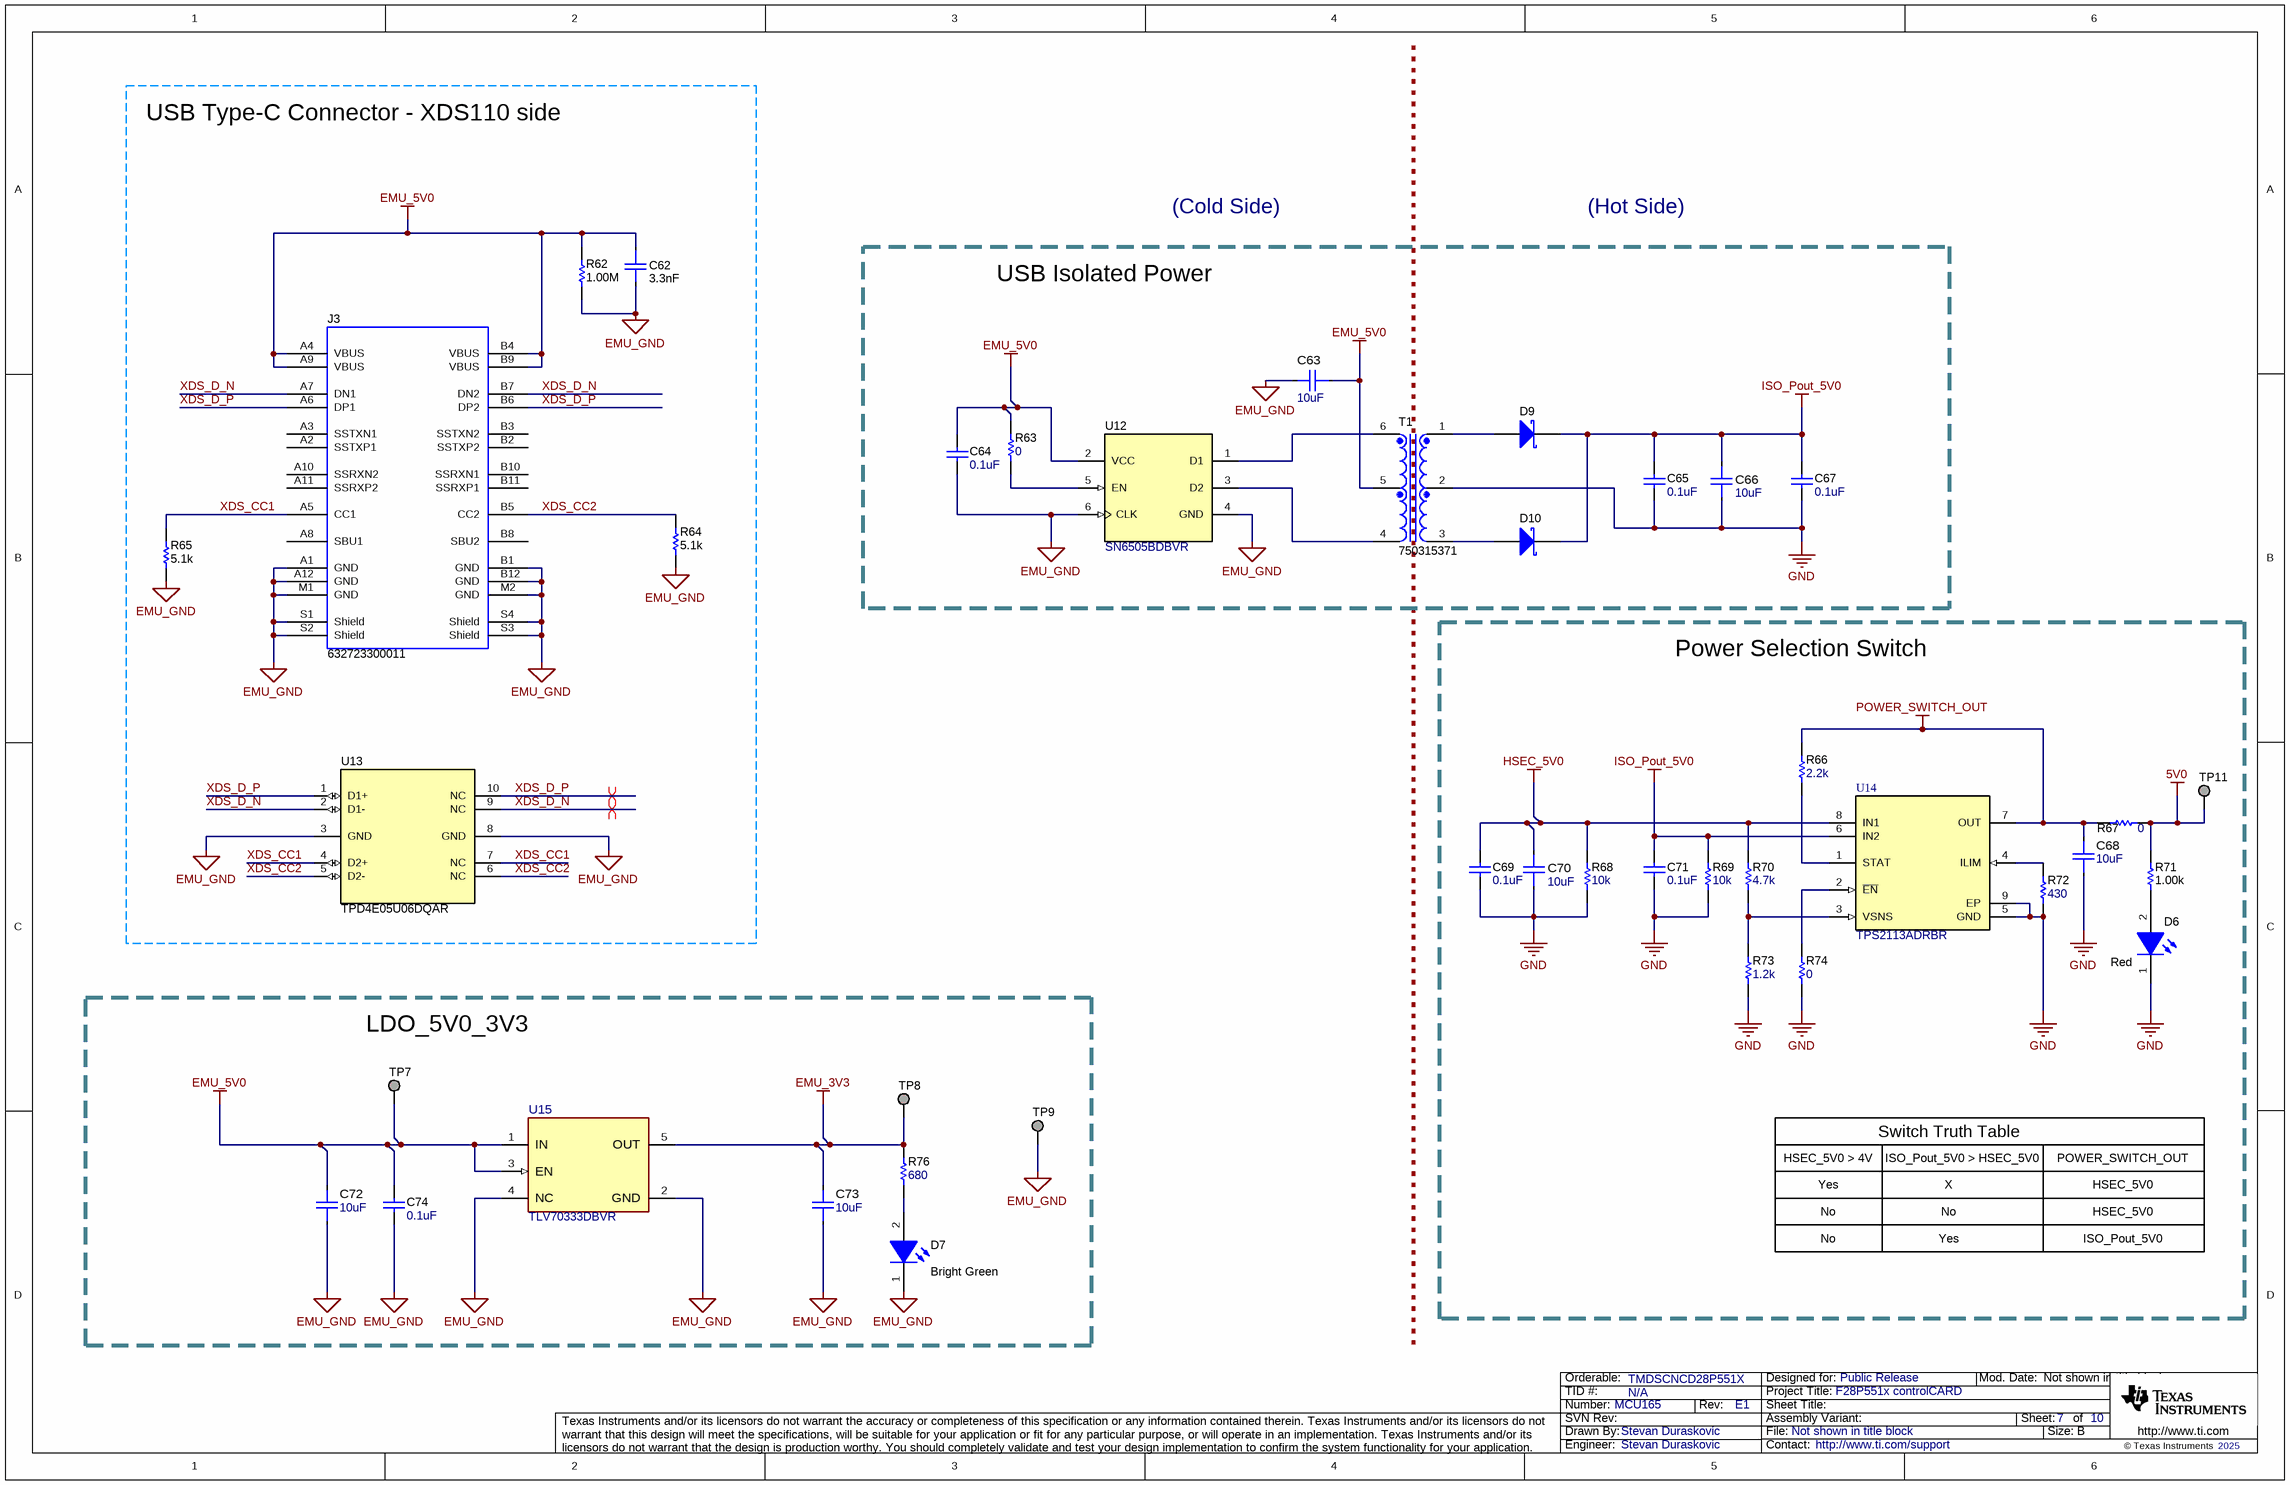
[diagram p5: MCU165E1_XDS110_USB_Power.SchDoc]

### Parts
C62  ValueDisplayed: 3.3nF  [FP-CL05B332KB5NNNC_0402-IPC_A]  (hidden comment: CL05B332KB5NNNC)
C63  ValueDisplayed: 10uF  [FP-CC0603KRX5R7BB106_0603-MFG]  (hidden comment: CC0603KRX5R7BB106)
C64  ValueDisplayed: 0.1uF  [0402]  (hidden comment: 885012205037)
C65  ValueDisplayed: 0.1uF  [0402]  (hidden comment: 885012205037)
C66  ValueDisplayed: 10uF  [FP-CC0603KRX5R7BB106_0603-MFG]  (hidden comment: CC0603KRX5R7BB106)
C67  ValueDisplayed: 0.1uF  [0402]  (hidden comment: 885012205037)
C68  ValueDisplayed: 10uF  [FP-CC0603KRX5R7BB106_0603-MFG]  (hidden comment: CC0603KRX5R7BB106)
C69  ValueDisplayed: 0.1uF  [0402]  (hidden comment: 885012205037)
C70  ValueDisplayed: 10uF  [FP-CC0603KRX5R7BB106_0603-MFG]  (hidden comment: CC0603KRX5R7BB106)
C71  ValueDisplayed: 0.1uF  [0402]  (hidden comment: 885012205037)
C72  ValueDisplayed: 10uF  [FP-CC0603KRX5R7BB106_0603-MFG]  (hidden comment: CC0603KRX5R7BB106)
C73  ValueDisplayed: 10uF  [FP-CC0603KRX5R7BB106_0603-MFG]  (hidden comment: CC0603KRX5R7BB106)
C74  ValueDisplayed: 0.1uF  [0402]  (hidden comment: 885012205037)
D6  value Red  [WL-SMCW_RED_0805]  (hidden comment: 150080SS75000)
D7  value Bright Green  [WL-SMCW_Green_0805]  (hidden comment: 150080VS75000)
D9  1N5819HW-7-F  [SOD-123]  (value not drawn)
D10  1N5819HW-7-F  [SOD-123]  (value not drawn)
J3  632723300011  [Wurth_632_723_300_011]
R62  ValueDisplayed: 1.00M  [0402]  (hidden comment: CRCW04021M00FKED)
R63  ValueDisplayed: 0  [0603]  (hidden comment: ERJ-3GEY0R00V)
R64  ValueDisplayed: 5.1k  [0603]  (hidden comment: RC0603JR-075K1L)
R65  ValueDisplayed: 5.1k  [0603]  (hidden comment: RC0603JR-075K1L)
R66  ValueDisplayed: 2.2k  [0603]  (hidden comment: CRCW06032K20JNEA)
R67  ValueDisplayed: 0  [0603]  (hidden comment: ERJ-3GEY0R00V)
R68  ValueDisplayed: 10k  [0603]  (hidden comment: CRCW060310K0JNEA)
R69  ValueDisplayed: 10k  [0603]  (hidden comment: CRCW060310K0JNEA)
R70  ValueDisplayed: 4.7k  [0603]  (hidden comment: RC0603JR-074K7L)
R71  ValueDisplayed: 1.00k  [0603]  (hidden comment: RC0603FR-071KL)
R72  ValueDisplayed: 430  [0603]  (hidden comment: RC0603FR-07430RL)
R73  ValueDisplayed: 1.2k  [0603]  (hidden comment: RC0603JR-071K2L)
R74  ValueDisplayed: 0  [0603]  (hidden comment: ERJ-3GEY0R00V)
R76  ValueDisplayed: 680  [0402]  (hidden comment: CRCW0402680RJNED)
T1  750315371  [Wurth_750315371]
TP7  TESTPOINT  [TP_50MIL-25MILHOLE]  (value not drawn)  (no BOM)
TP8  TESTPOINT  [TP_50MIL-25MILHOLE]  (value not drawn)  (no BOM)
TP9  TESTPOINT  [TP_50MIL-25MILHOLE]  (value not drawn)  (no BOM)
TP11  TESTPOINT  [TP_50MIL-25MILHOLE]  (value not drawn)  (no BOM)
U12  SN6505BDBVR  [DBV0006A_L]
U13  TPD4E05U06DQAR  [DQA0010A]
U14  TPS2113ADRBR  [DRB0008B]
U15  TLV70333DBVR  [DBV0005A-MFG]

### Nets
5V0: R67.1 R71.2 TP11.1
EMU_3V3: C73.2 R76.1 TP8.1 U15.5(OUT)
EMU_5V0: C62.1 C63.1 C64.1 C72.2 C74.1 J3.A4(VBUS) J3.A9(VBUS) J3.B4(VBUS) J3.B9(VBUS) R62.2 R63.2 T1.5 TP7.1 U12.2(VCC) U15.1(IN) U15.3(EN)
EMU_GND: C62.2 C63.2 C64.2 C72.1 C73.1 C74.2 D7.1(K) J3.A1(GND) J3.A12(GND) J3.B1(GND) J3.B12(GND) J3.M1(GND) J3.M2(GND) J3.S1(Shield) J3.S2(Shield) J3.S3(Shield) J3.S4(Shield) R62.1 R64.1 R65.1 TP9.1 U12.4(GND) U12.6(CLK) U13.3(GND) U13.8(GND) U15.2(GND) U15.4(NC)
GND: C65.2 C66.1 C67.2 C68.1 C69.2 C70.1 C71.2 D6.1(K) R68.1 R69.1 R72.1 R73.1 R74.1 T1.2 U14.5(GND) U14.9(EP)
HSEC_5V0: C69.1 C70.2 R68.2 R70.2 U14.8(IN1)
ISO_Pout_5V0: C65.1 C66.2 C67.1 C71.1 D9.1(K) D10.1(K) R69.2 U14.6(IN2)
POWER_SWITCH_OUT: C68.2 R66.2 R67.2 U14.7(OUT)
XDS_CC1: J3.A5(CC1) R65.2 U13.4(D2+) U13.7(NC)
XDS_CC2: J3.B5(CC2) R64.2 U13.5(D2-) U13.6(NC)
XDS_D_N: J3.A7(DN1) J3.B7(DN2) U13.2(D1-) U13.9(NC)
XDS_D_P: J3.A6(DP1) J3.B6(DP2) U13.1(D1+) U13.10(NC)
NetD6_2: D6.2(A) R71.1
NetD7_2: D7.2(A) R76.2
NetD9_2: D9.2(A) T1.1
NetD10_2: D10.2(A) T1.3
NetR63_1: R63.1 U12.5(EN)
NetR66_1: R66.1 U14.1(STAT)
NetR70_1: R70.1 R73.2 U14.3(VSNS)
NetR72_2: R72.2 U14.4(ILIM)
NetR74_2: R74.2 U14.2(~{EN})
NetT1_4: T1.4 U12.3(D2)
NetT1_6: T1.6 U12.1(D1)

Not connected (* = marked no-connect by the designer): J3 A2(SSTXP1) A3(SSTXN1) A8(SBU1) A10(SSRXN2) A11(SSRXP2) B2(SSTXP2) B3(SSTXN2) B8(SBU2) B10(SSRXN1) B11(SSRXP1)

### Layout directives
differential pair: XDS_D_N, XDS_D_P

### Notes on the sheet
- USB Type-C Connector - XDS110 side
- (Cold Side)
- (Hot Side)
- USB Isolated Power
- Power Selection Switch
- LDO_5V0_3V3
- HSEC_5V0 > 4V
- Switch Truth Table
- ISO_Pout_5V0 > HSEC_5V0
- POWER_SWITCH_OUT
- Yes
- No
- X
- HSEC_5V0
- ISO_Pout_5V0

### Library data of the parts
C62 = CMP-0092214-1: Cap Ceramic 3.3nF 50V X7R ±10% SMD 0402 +125°C Paper T/R; Manufacturer: Samsung; TempCo: 15%; SizeZ_mm: 0.55mm; AEC Qualified: No
C63 C66 C68 C70 C72 C73 = CMP-0001560-1: as C6 on sheet MCU165E1_Power
C64 C65 C67 C69 C71 C74 = CMP-0006228-2: as C2 on sheet MCU165E1_Support
D6 = CMP-0002951-3: LED, Red, SMD; Manufacturer: Wurth Elektronik; Type: AlInGaP; Angle: 140; Vr_V: 5V; Ir_A: 25µA; Vf_V: 1.9V; Value1: 0.072W; Tjmax_C: 85°C; Io_A: 30mA; Power_TotalModule: 72mW
D7 = CMP-0002960-2: as D3 on sheet MCU165E1_Power
D9 D10 = CMP-0028360-2: Diode, Schottky, 40 V, 1 A, SOD-123; Manufacturer: Diodes Inc.; Green_Lifecycle: Active; AEC Category: Q101; TJmax_C: 125°C; SizeArea_mm2: 6.545; Vr_V: 40V; Value1: 1A; SizeZ_mm: 1.35; Value: 40V; Vf_V: 450mV; SizeX_mm: 3.85; Green_REACh: Passed; Value2: 0.45V; SizeY_mm: 1.7; SizeAreaWB_mm2: 13.095
J3 = CMP-0080891-1: Connector, Receptacle, USB Type C, R/A; Manufacturer: Wurth Elektronik; Current_A: 3A; Gender: Female; Voltage_V: 5V; ContactFinish: Gold; Cert_UL: Y
R62 = CMP-0026100-2: RES, 1.00 M, 1%, 0.063 W, AEC-Q200 Grade 0, 0402; Manufacturer: Vishay-Dale; Value: 1.00Meg; Res_ohm: 1M; Value_Code: 1M00; Power_W: 63mW; Value2: 0.063W; VDC_V: 50V; TempCo: 100 ppm/C; SizeArea_mm2: 0.5; SizeX_mm: 1; SizeZ_mm: 0.6; EIA_Code: E96; AEC Category: Q200; AEC Qualified: Y; AEC Grade: 0
R63 R67 R74 = CMP-0025874-4: as R23 on sheet MCU165E1_Support
R64 R65 = CMP-0025932-5: RES, 5.1 k, 5%, 0.1 W, 0603; Manufacturer: Yageo; Power_W: 100mW; TempCo: 100 ppm/C; Value_Code: 5k10; Value: 5.1k; EIA_Code: E24; SizeX_mm: 1.6; SizeY_mm: 0.8; SizeZ_mm: 1; Value2: 0.1W; SizeArea_mm2: 1.28; AEC Qualified: N; VDC_V: 75V; AEC Category: Q200; SizeAreaWB_mm2: 4.68
R66 = CMP-0025769-4: RES, 2.2 k, 5%, 0.1 W, AEC-Q200 Grade 0, 0603; Manufacturer: Vishay-Dale; Power_W: 100mW; TempCo: 200 ppm/C; Value_Code: 2k20; Value: 2.2k; EIA_Code: E24; SizeX_mm: 1.6; SizeY_mm: 0.8; SizeZ_mm: 1; Value2: 0.1W; SizeArea_mm2: 1.28; AEC Qualified: Y; VDC_V: 75V; AEC Category: Q200; AEC Grade: 0
R68 R69 = CMP-0025701-4: RES, 10 k, 5%, 0.1 W, AEC-Q200 Grade 0, 0603; Manufacturer: Vishay-Dale; Power_W: 100mW; TempCo: 200 ppm/C; Value_Code: 10k0; Value: 10k; EIA_Code: E24; SizeX_mm: 1.6; SizeY_mm: 0.8; SizeZ_mm: 1; Value2: 0.1W; SizeArea_mm2: 1.28; AEC Qualified: Y; VDC_V: 75V; AEC Category: Q200; AEC Grade: 0
R70 = CMP-0025927-5: RES, 4.7 k, 5%, 0.1 W, 0603; Manufacturer: Yageo; Power_W: 100mW; TempCo: 100 ppm/C; Value_Code: 4k70; Value: 4.7k; EIA_Code: E24; SizeX_mm: 1.6; SizeY_mm: 0.8; SizeZ_mm: 1; Value2: 0.1W; SizeArea_mm2: 1.28; AEC Qualified: N; VDC_V: 75V; AEC Category: Q200; SizeAreaWB_mm2: 4.68
R71 = CMP-0022895-5: RES, 1.00 k, 1%, 0.1 W, 0603; Manufacturer: Yageo; Power_W: 100mW; TempCo: 100 ppm/C; Value_Code: 1k00; Value: 1.00k; EIA_Code: E96; Res_ohm: 1k; SizeX_mm: 1.6; SizeY_mm: 0.8; SizeZ_mm: 1; Value2: 0.1W; SizeArea_mm2: 1.28; AEC Qualified: N; VDC_V: 75V; AEC Category: Q200; SizeAreaWB_mm2: 4.68
R72 = CMP-0023109-5: RES, 430, 1%, 0.1 W, 0603; Manufacturer: Yageo; Power_W: 100mW; TempCo: 100 ppm/C; Value_Code: 430R; Value: 430; SizeX_mm: 1.6; SizeY_mm: 0.8; SizeZ_mm: 1; Value2: 0.1W; SizeArea_mm2: 1.28; AEC Qualified: N; VDC_V: 75V; AEC Category: Q200; SizeAreaWB_mm2: 4.68
R73 = CMP-0025894-5: RES, 1.2 k, 5%, 0.1 W, 0603; Manufacturer: Yageo; Power_W: 100mW; TempCo: 100 ppm/C; Value_Code: 1k20; Value: 1.2k; EIA_Code: E24; SizeX_mm: 1.6; SizeY_mm: 0.8; SizeZ_mm: 1; Value2: 0.1W; SizeArea_mm2: 1.28; AEC Qualified: N; VDC_V: 75V; AEC Category: Q200; SizeAreaWB_mm2: 4.68
R76 = CMP-0026962-3: RES, 680, 5%, 0.063 W, AEC-Q200 Grade 0, 0402; Manufacturer: Vishay-Dale; Value: 680; Value_Code: 680R; Power_W: 63mW; Value2: 0.063W; VDC_V: 50V; TempCo: 200 ppm/C; EIA_Code: E24; AEC Category: Q200; AEC Qualified: Y; AEC Grade: 0; SizeArea_mm2: 0.5; SizeX_mm: 1; SizeZ_mm: 0.6
T1 = CMP-0030623-1: Transformer, 105uH, TH; Manufacturer: Wurth Elektronik; Green_Lifecycle: Active; DCR_ohm: 60m; Green_REACh: Passed; Lp: 105; Ns1toNp: 1.1; Ind_H: 105µH
TP7-TP9 TP11 = CMP-0078143-3: TEST POINT.  No entry in BOM.
U12 = CMP-0076095-1: Low-Noise 1 A, 420 kHz Transformer Driver, DBV0006A (SOT-23-6); Manufacturer: Texas Instruments; Alternate PartNumber: SN6505BDBVT; SizeAreaWB_mm2: 14.82; SizeArea_mm2: 8.12; SizeZ_mm: 1.45; Green_REACh: Passed; SizeY_mm: 2.9; Green_Lifecycle: Active; U/M: EA; CompType: IC; SizeX_mm: 2.8
U13 = CMP-0073613-3: 4-Channel Ultra-Low-Capacitance IEC ESD Protection Diode, DQA0010A (USON-10); Alternate Manufacturer: Texas Instruments; Green_Lifecycle: Active; SizeAreaWB_mm2: 7.0; Green_REACh: Passed; SizeZ_mm: 0.55; SizeX_mm: 1.0; SizeY_mm: 2.5; CompType: IC; AEC Category: Q200; AEC Qualified: N
U14 = CMP-0043361-3: Dual In / Single Out Autoswitching Power Mux, 2.8 to 5.5 V, -40 to 85 degC, 9-pin SON (DRB), Green (RoHS & no Sb/Br); Manufacturer: Texas Instruments; SubFamily: Power Multiplexer (MUX); IN1 Output Current(Max)(A): 1.25; IN1, IN2 Input Voltage(Min)(V): 2.8; IN2 rDS(on)(Typ)(Ohms): 0.084; Number of Inputs: 2; IN1, IN2 Input Voltage(Max)(V): 5.5; IN1 rDS(on)(Typ)(mOhm): 84; AEC Category: Q200; AEC Qualified: N; CompType: IC; SizeAreaWB_mm2: 16.0; SizeArea_mm2: 9.0; SizeX_mm: 3.0; SizeZ_mm: 1.0
U15 = CMP-0091939-1: Linear Voltage Regulator IC Positive Fixed 1 Output 300mA SOT-23-5; Manufacturer: Texas Instruments; SizeZ_mm: 1.45mm; Nominal Supply Current: 35-370uA; TJmax_C: +125°C; Output Voltage: 3.3V; Dropout Voltage: 260mV; Standoff Height: 0mm; Accuracy Percentage: 2%; AEC Qualified: No; Max Supply Voltage: 5.5V; Number Of Outputs: 1; Min Supply Voltage: 2V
